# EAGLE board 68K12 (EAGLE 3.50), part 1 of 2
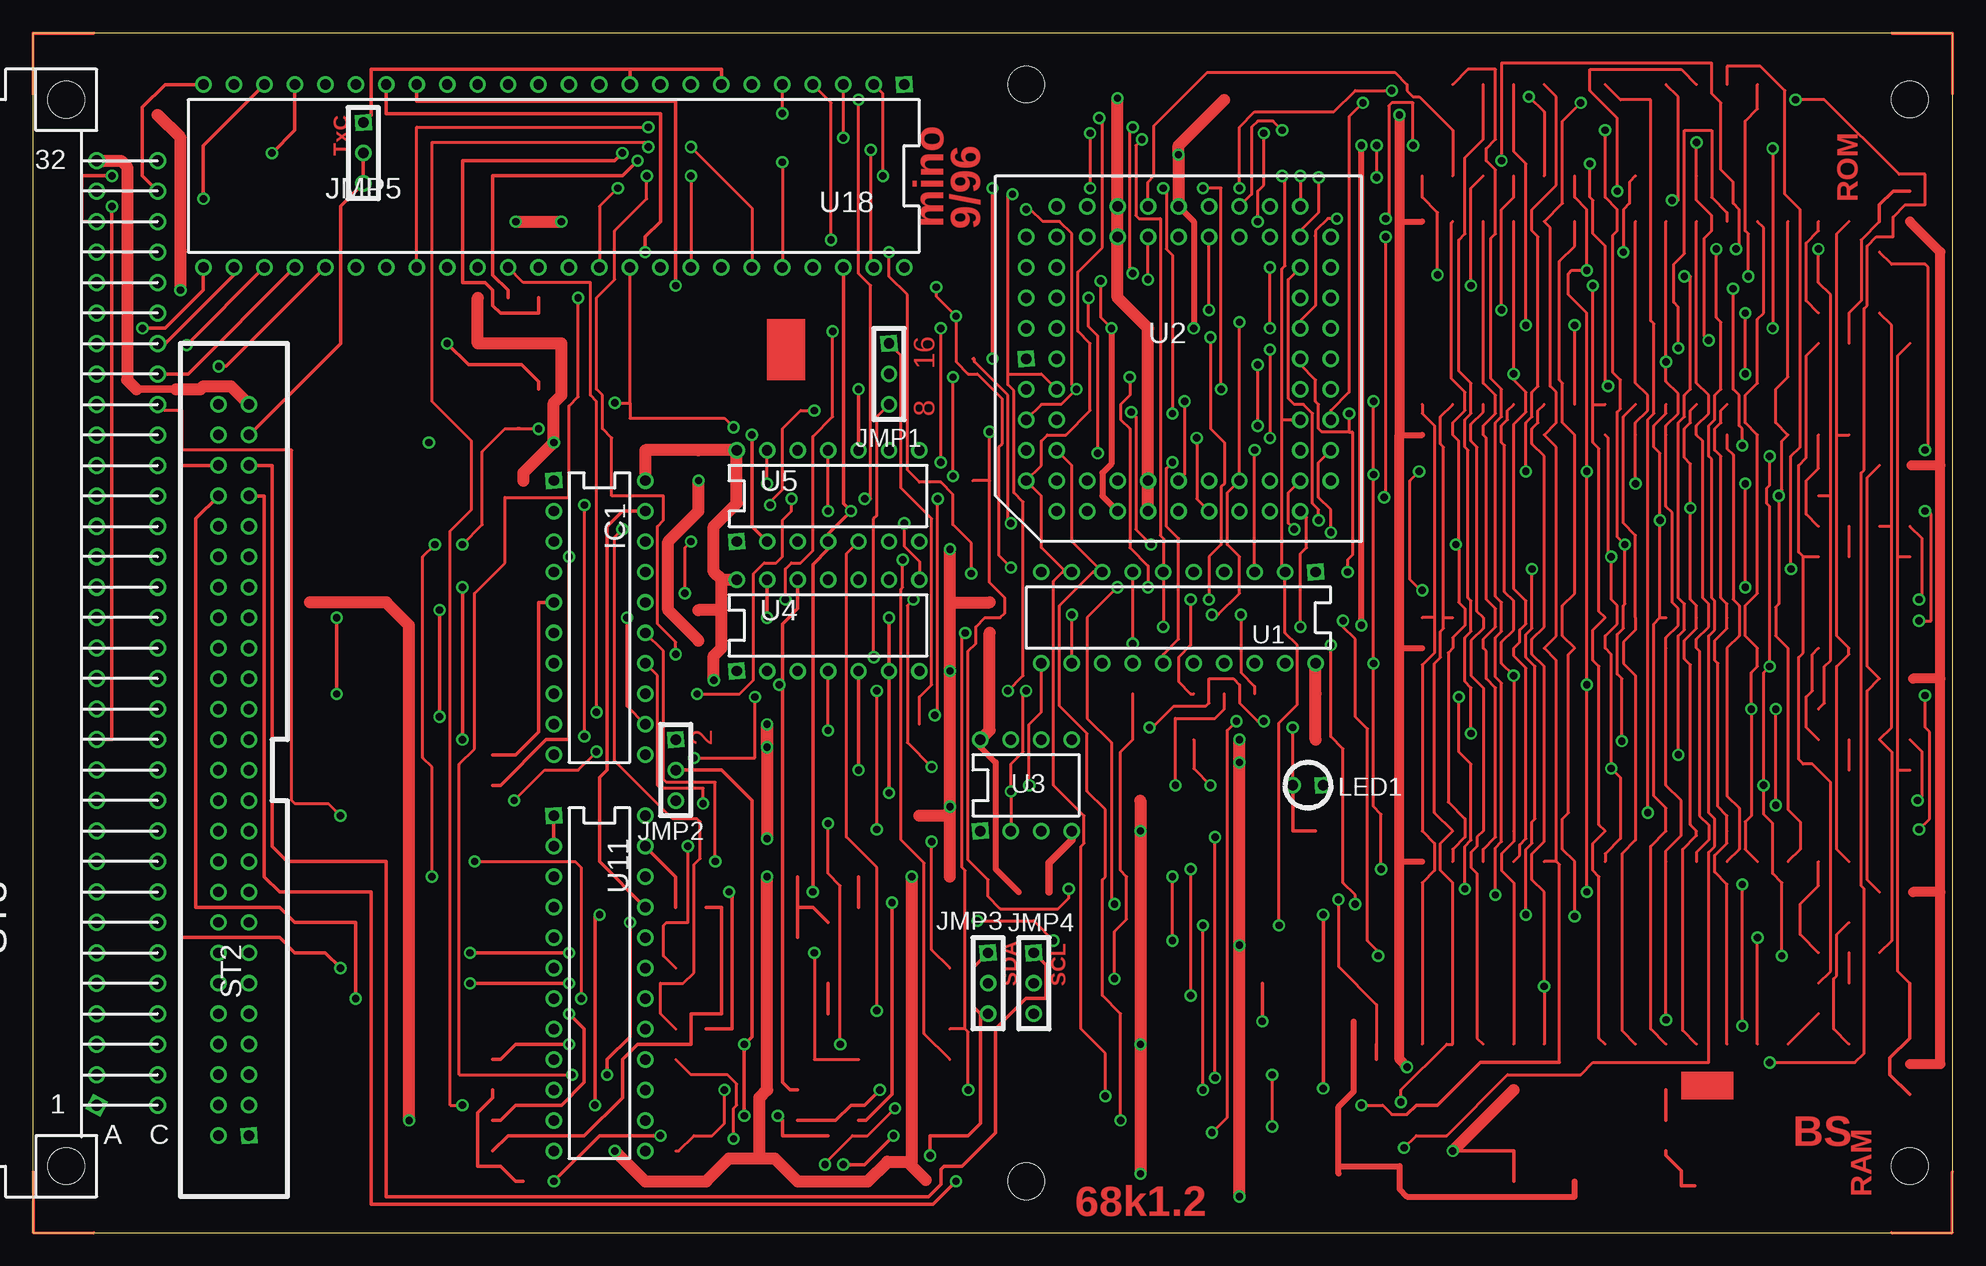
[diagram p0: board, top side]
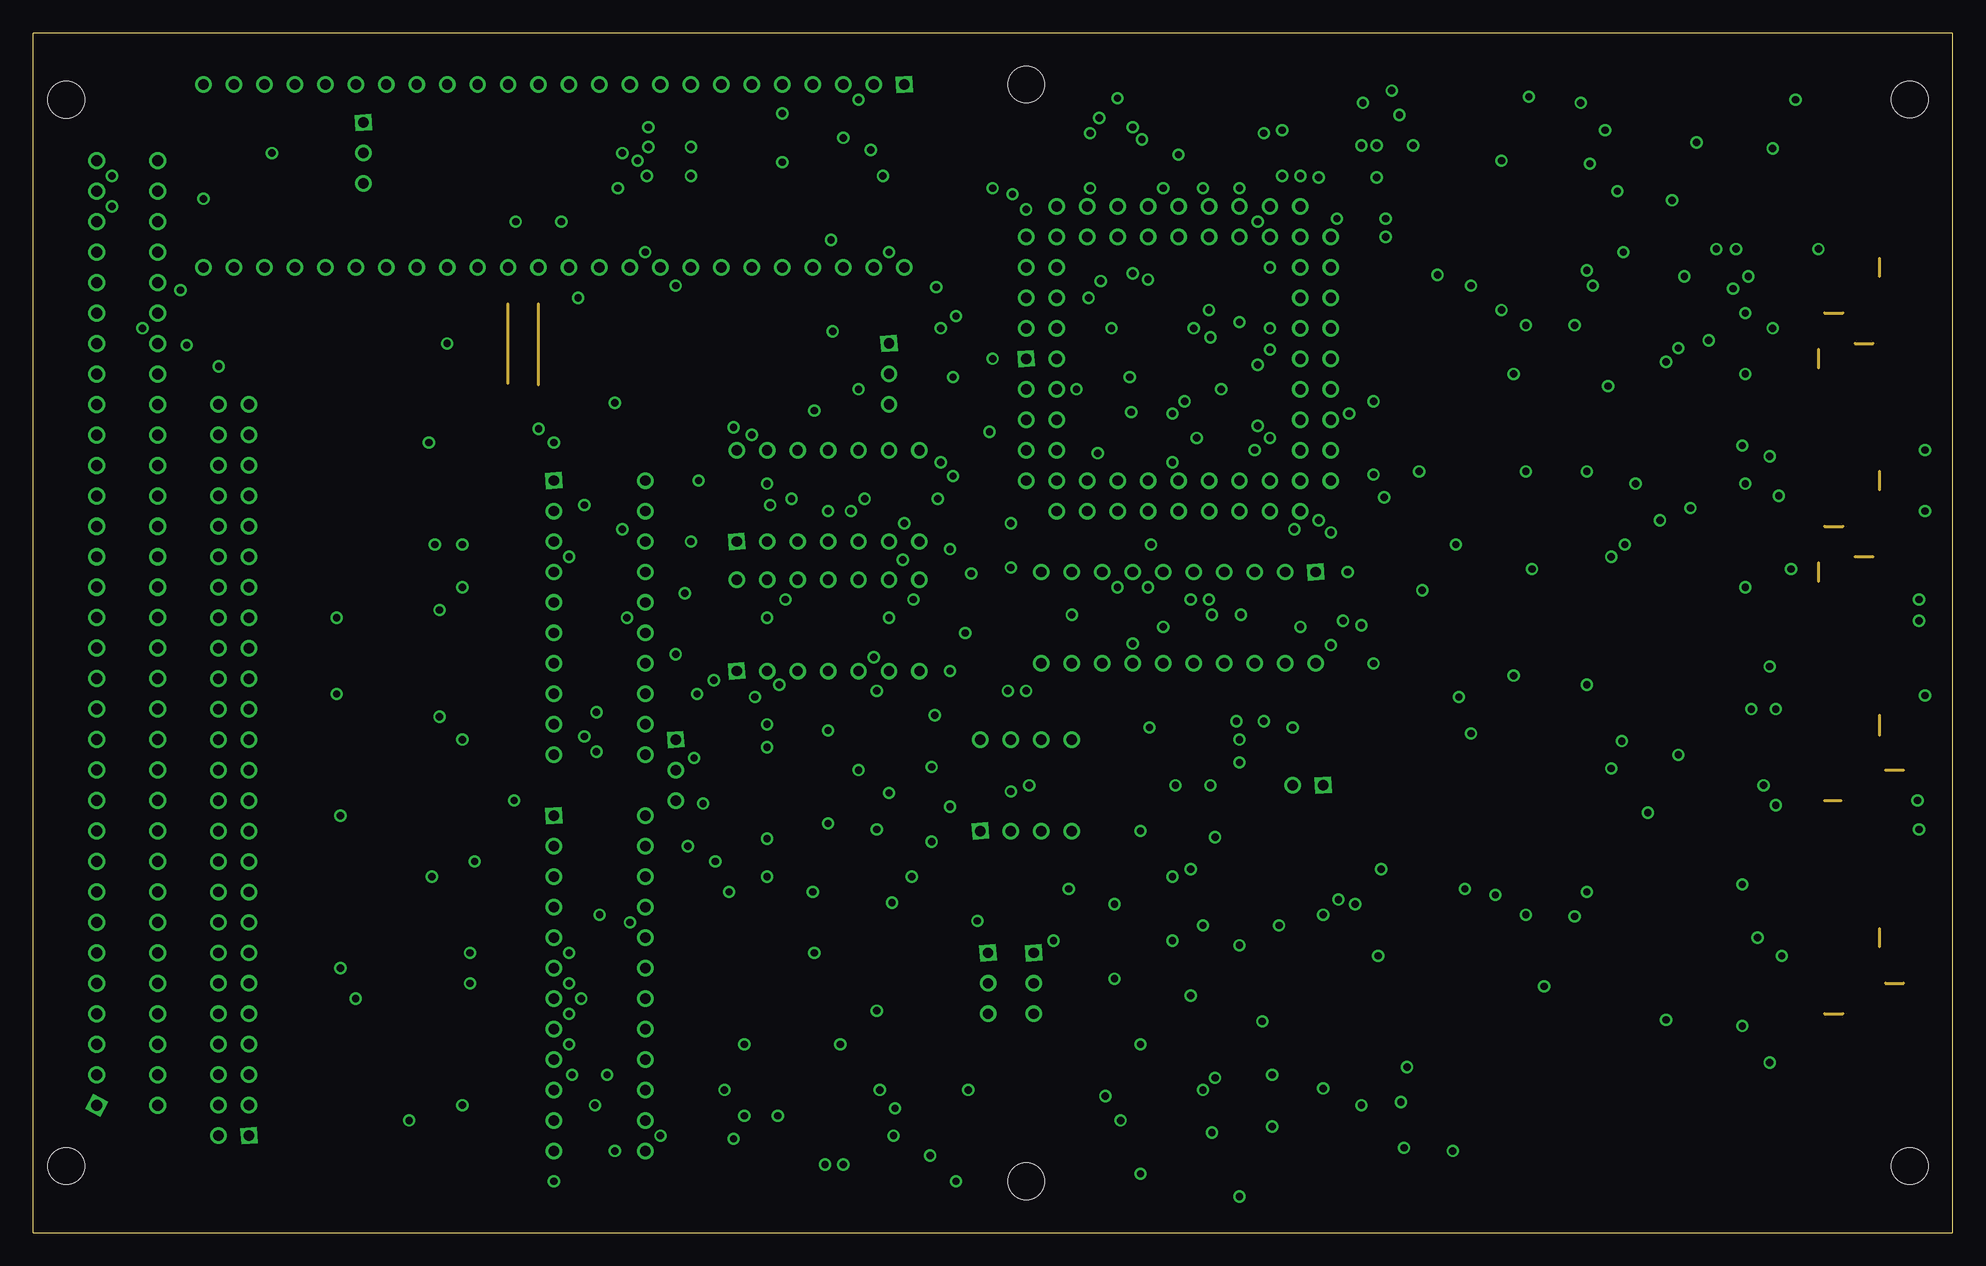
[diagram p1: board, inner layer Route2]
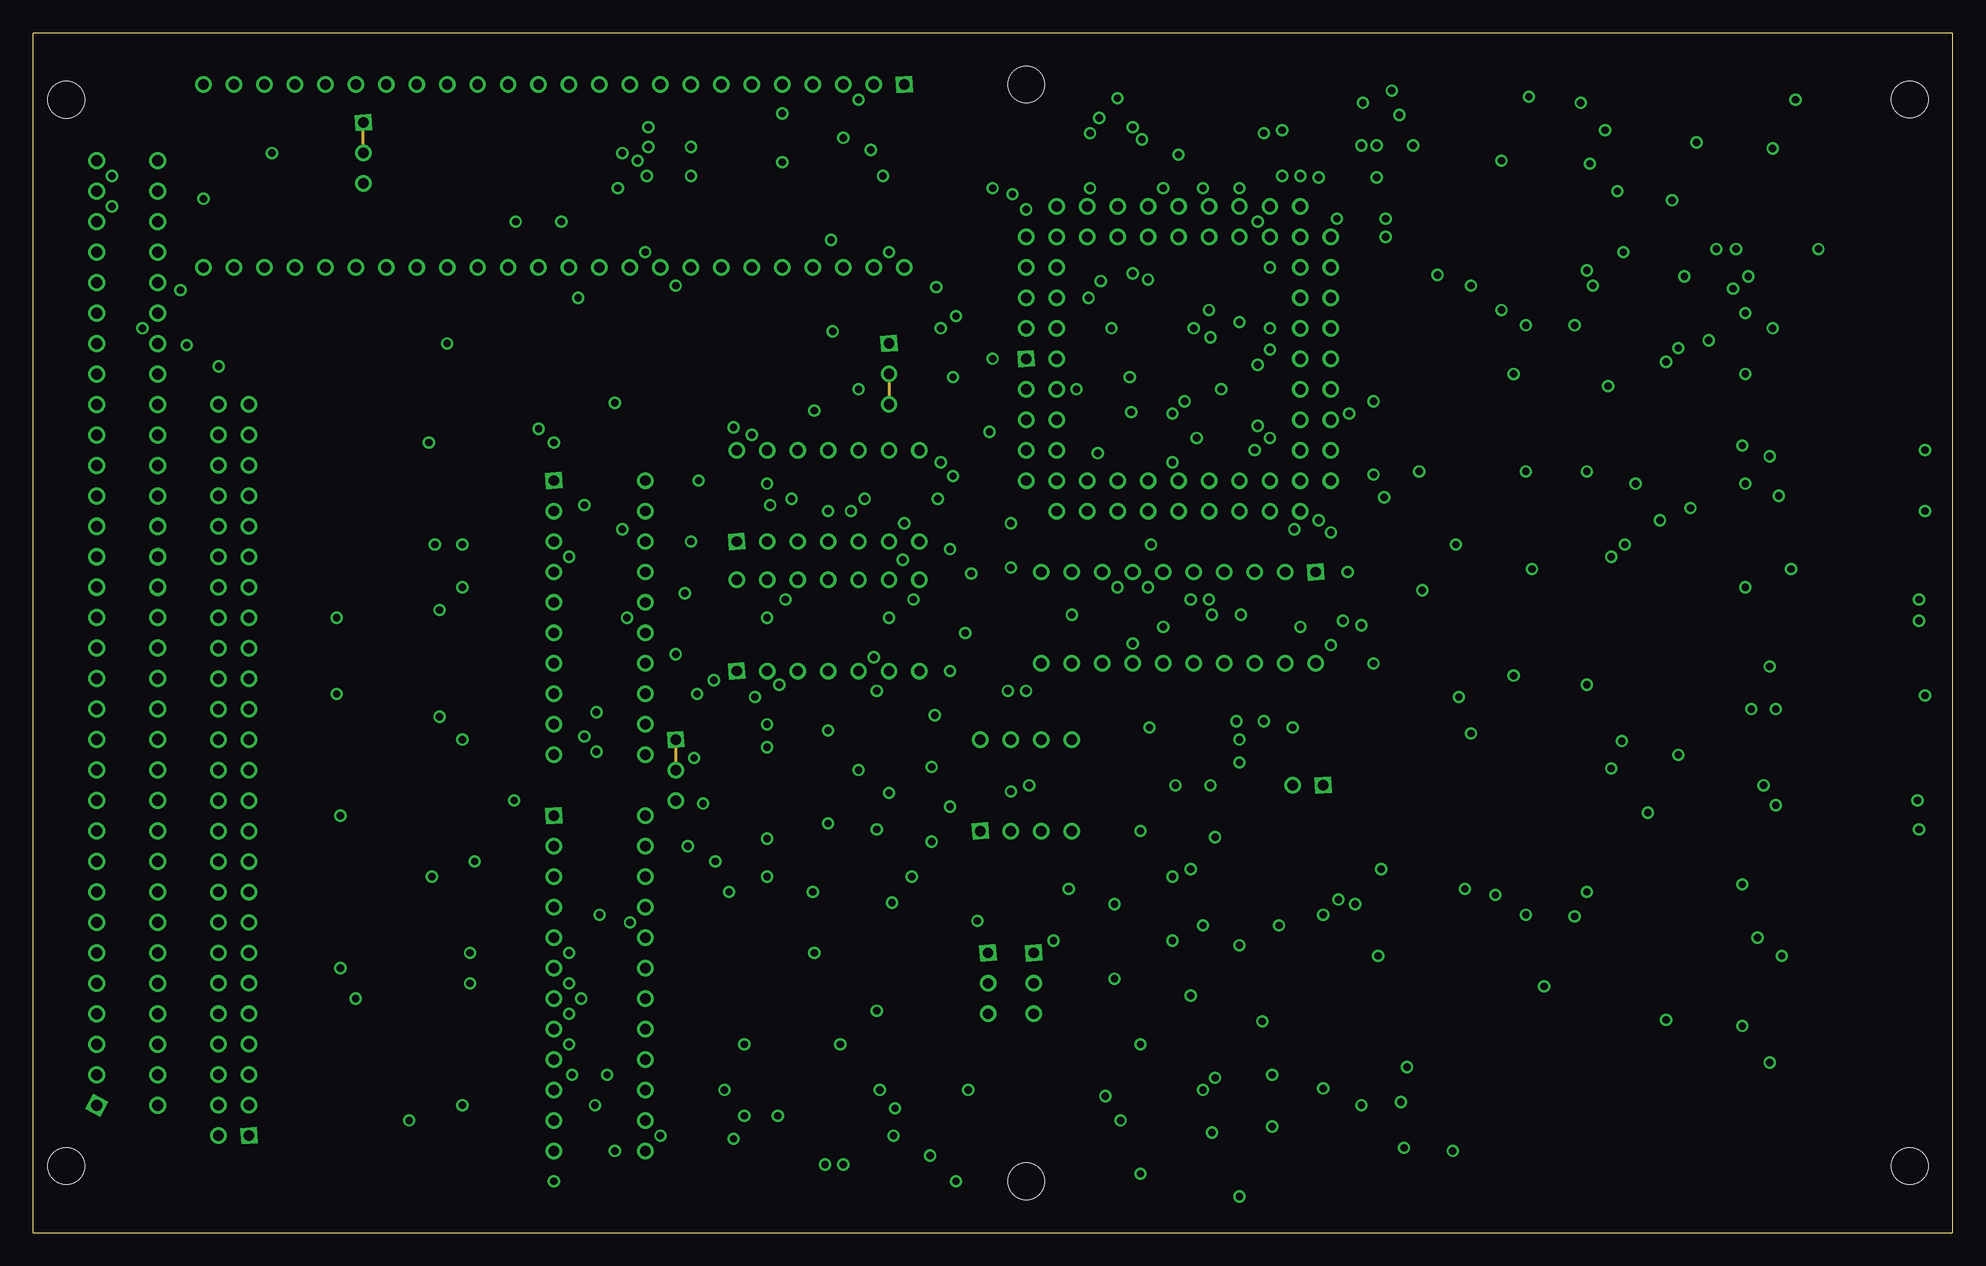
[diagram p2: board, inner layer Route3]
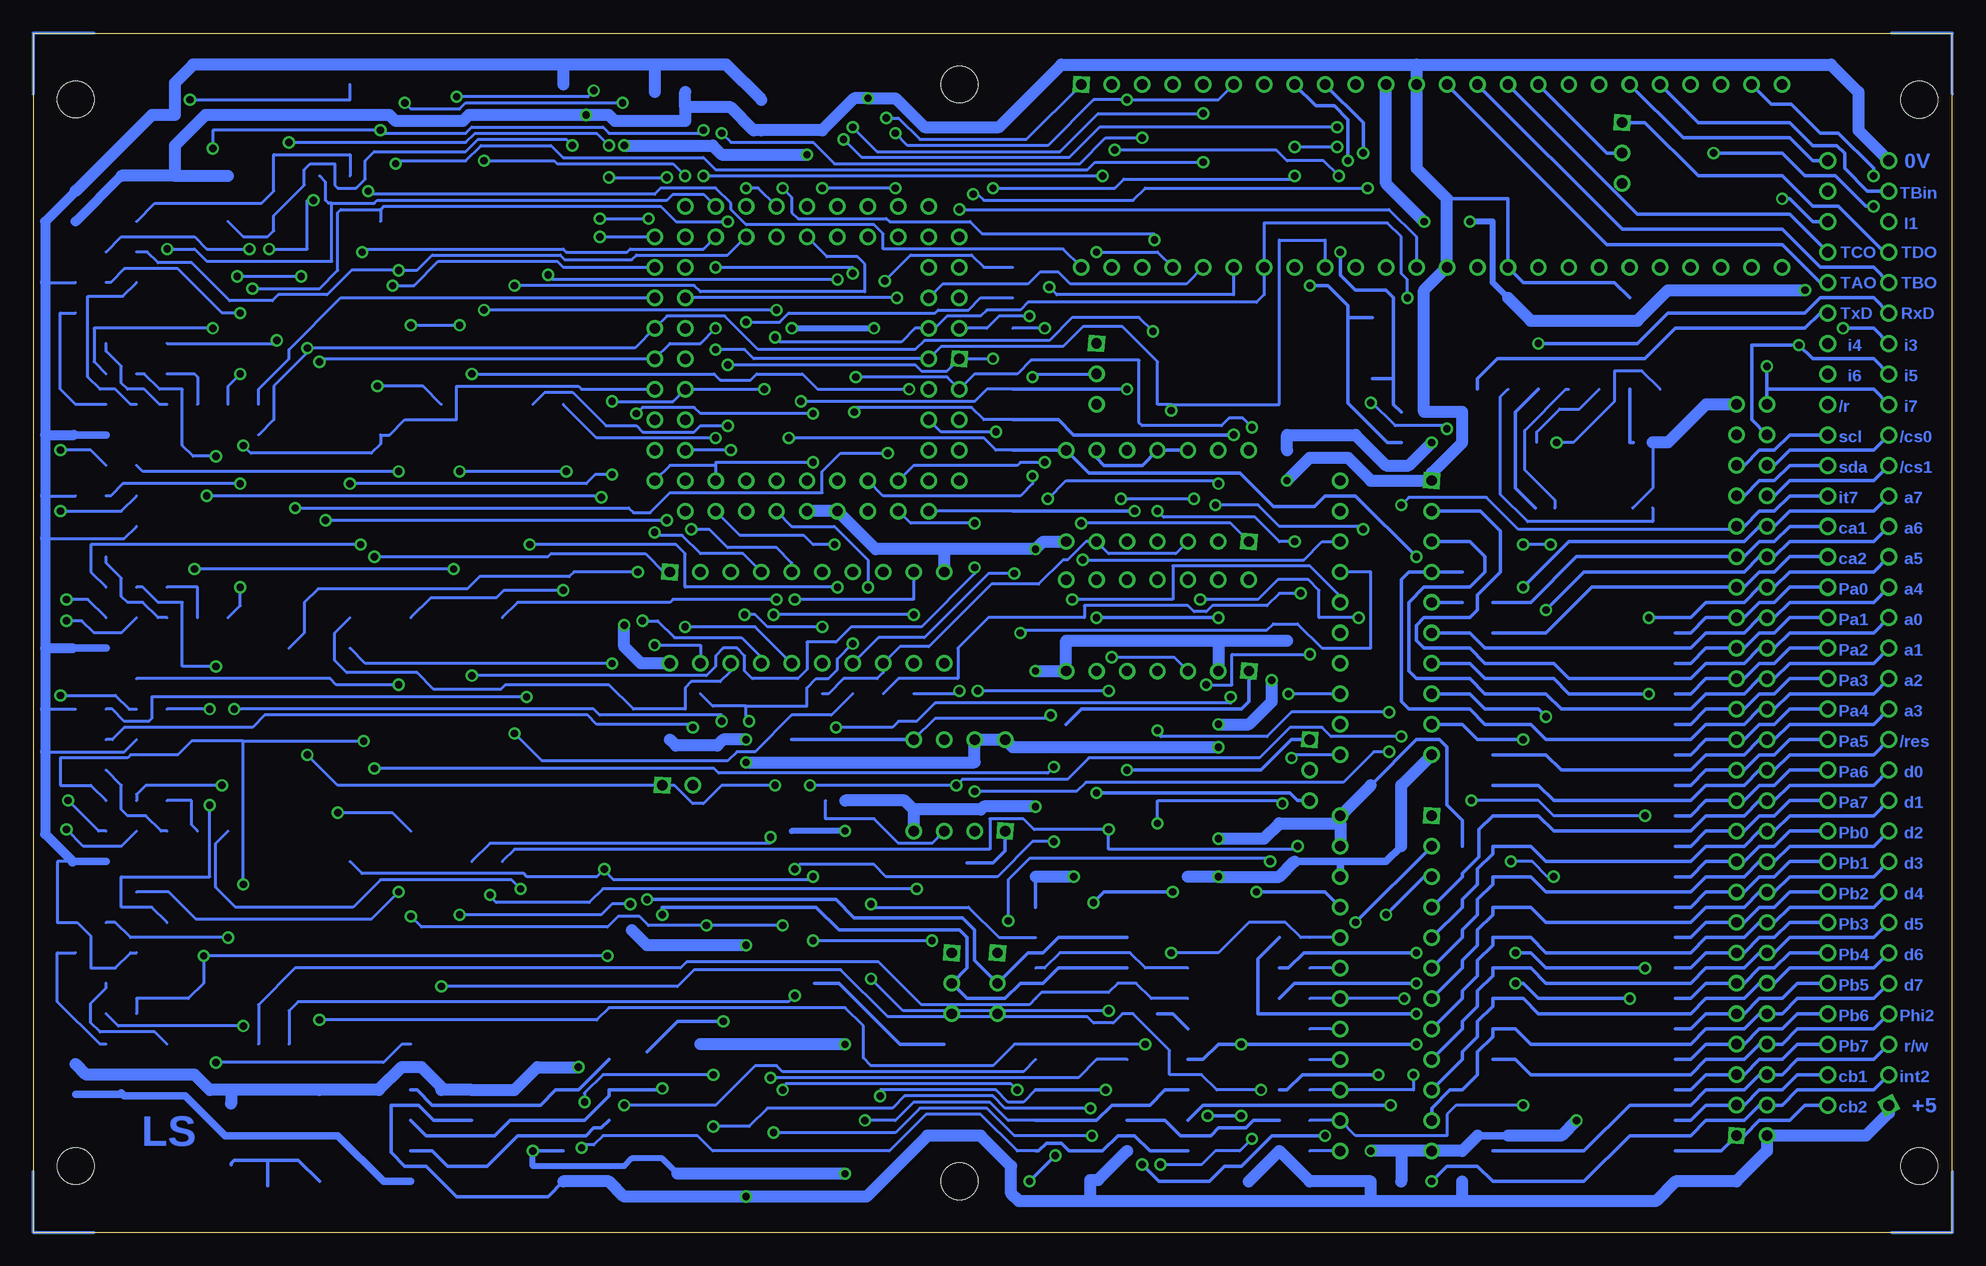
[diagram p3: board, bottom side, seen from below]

Size 159.99 x 100 mm. Coordinates in mm from the lower left corner, seen from the top.
Outline: 0,0 159.99,0 159.99,100 0,100 0,0
Copper layers used: Top, Route2, Route3, Bottom
Holes 3.05 mm at 156.44,5.54 156.44,94.46 82.78,95.71 82.78,4.27
tRestrict: area 49.8,69 to 65,79.2; area 80.2,1.7 to 85.4,6.9; area 80.2,93.1 to 85.4,98.3; area 153.6,2.7 to 159.3,8.4; area 153.6,91.6 to 159.3,97.3
bRestrict: area 80.2,1.7 to 85.4,6.9; area 80.2,93.1 to 85.4,98.3; area 153.6,2.7 to 159.3,8.4; area 153.6,91.6 to 159.3,97.3

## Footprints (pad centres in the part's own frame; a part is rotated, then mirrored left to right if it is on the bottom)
L20 = drill 0.864 pad 1.321 square:  0,0 | drill 0.864 pad 1.321 round:  2.54,0;  5.08,0;  7.62,0;  10.16,0;  12.7,0;  15.24,0;  17.78,0;  20.32,0;  22.86,0;  22.86,7.62;  20.32,7.62;  17.78,7.62;  15.24,7.62;  12.7,7.62;  10.16,7.62;  7.62,7.62;  5.08,7.62;  2.54,7.62;  0,7.62
1 = drill 0.864 pad 1.321 square:  0,0 | drill 0.864 pad 1.321 round:  2.54,0;  5.08,0
D3 = drill 0.864 pad 1.321 square:  0,0 | drill 0.864 pad 1.321 round:  2.54,0
NNE50S = drill 0.864 pad 1.321 square:  3.81,2.54 | drill 0.864 pad 1.321 round:  3.81,5.08;  6.35,2.54;  6.35,5.08;  8.89,2.54;  8.89,5.08;  11.43,2.54;  11.43,5.08;  13.97,2.54;  13.97,5.08;  16.51,2.54;  16.51,5.08;  19.05,2.54;  19.05,5.08;  21.59,2.54;  21.59,5.08;  24.13,2.54;  24.13,5.08;  26.67,2.54;  26.67,5.08;  29.21,2.54;  29.21,5.08;  31.75,2.54;  31.75,5.08;  34.29,2.54;  34.29,5.08;  36.83,2.54;  36.83,5.08;  39.37,2.54;  39.37,5.08;  41.91,2.54;  41.91,5.08;  44.45,2.54;  44.45,5.08;  46.99,2.54;  46.99,5.08;  49.53,2.54;  49.53,5.08;  52.07,2.54;  52.07,5.08;  54.61,2.54;  54.61,5.08;  57.15,2.54;  57.15,5.08;  59.69,2.54;  59.69,5.08;  62.23,2.54;  62.23,5.08;  64.77,2.54;  64.77,5.08
64ACST = drill 0.914 pad 1.422 square:  0,0 | drill 0.914 pad 1.422 round:  0,2.54;  0,5.08;  0,7.62;  0,10.16;  0,12.7;  0,15.24;  0,17.78;  0,20.32;  0,22.86;  0,25.4;  0,27.94;  0,30.48;  0,33.02;  0,35.56;  0,38.1;  0,40.64;  0,43.18;  0,45.72;  0,48.26;  0,50.8;  0,53.34;  0,55.88;  0,58.42;  0,60.96;  0,63.5;  0,66.04;  0,68.58;  0,71.12;  0,73.66;  0,76.2;  0,78.74;  5.08,0;  5.08,2.54;  5.08,5.08;  5.08,7.62;  5.08,10.16;  5.08,12.7;  5.08,15.24;  5.08,17.78;  5.08,20.32;  5.08,22.86;  5.08,25.4;  5.08,27.94;  5.08,30.48;  5.08,33.02;  5.08,35.56;  5.08,38.1;  5.08,40.64;  5.08,43.18;  5.08,45.72;  5.08,48.26;  5.08,50.8;  5.08,53.34;  5.08,55.88;  5.08,58.42;  5.08,60.96;  5.08,63.5;  5.08,66.04;  5.08,68.58;  5.08,71.12;  5.08,73.66;  5.08,76.2;  5.08,78.74 | hole 3.048: -2.54,-5.08; -2.54,83.82
P20 = drill 0.864 pad 1.321 square:  0,0 | drill 0.864 pad 1.321 round:  2.54,0;  5.08,0;  7.62,0;  10.16,0;  12.7,0;  15.24,0;  17.78,0;  20.32,0;  22.86,0;  22.86,7.62;  20.32,7.62;  17.78,7.62;  15.24,7.62;  12.7,7.62;  10.16,7.62;  7.62,7.62;  5.08,7.62;  2.54,7.62;  0,7.62
CC68 = drill 0.864 pad 1.321 square:  10.16,0 | drill 0.864 pad 1.321 round:  10.16,2.54;  12.7,0;  12.7,2.54;  15.24,0;  15.24,2.54;  17.78,0;  17.78,2.54;  20.32,0;  22.86,2.54;  20.32,2.54;  22.86,5.08;  20.32,5.08;  22.86,7.62;  20.32,7.62;  22.86,10.16;  20.32,10.16;  22.86,12.7;  20.32,12.7;  22.86,15.24;  20.32,15.24;  22.86,17.78;  20.32,17.78;  22.86,20.32;  20.32,20.32;  22.86,22.86;  20.32,25.4;  20.32,22.86;  17.78,25.4;  17.78,22.86;  15.24,25.4;  15.24,22.86;  12.7,25.4;  12.7,22.86;  10.16,25.4;  10.16,22.86;  7.62,25.4;  7.62,22.86;  5.08,25.4;  5.08,22.86;  2.54,25.4;  2.54,22.86;  0,25.4;  -2.54,22.86;  0,22.86;  -2.54,20.32;  0,20.32;  -2.54,17.78;  0,17.78;  -2.54,15.24;  0,15.24;  -2.54,12.7;  0,12.7;  -2.54,10.16;  0,10.16;  -2.54,7.62;  0,7.62;  -2.54,5.08;  0,5.08;  -2.54,2.54;  0,0;  0,2.54;  2.54,0;  2.54,2.54;  5.08,0;  5.08,2.54;  7.62,0;  7.62,2.54
L8 = drill 0.864 pad 1.321 square:  0,0 | drill 0.864 pad 1.321 round:  2.54,0;  5.08,0;  7.62,0;  7.62,7.62;  5.08,7.62;  2.54,7.62;  0,7.62
L14 = drill 0.864 pad 1.321 square:  0,0 | drill 0.864 pad 1.321 round:  2.54,0;  5.08,0;  7.62,0;  10.16,0;  12.7,0;  15.24,0;  15.24,7.62;  12.7,7.62;  10.16,7.62;  7.62,7.62;  5.08,7.62;  2.54,7.62;  0,7.62
L24S = drill 0.864 pad 1.321 square:  0,0 | drill 0.864 pad 1.321 round:  2.54,0;  5.08,0;  7.62,0;  10.16,0;  12.7,0;  15.24,0;  17.78,0;  20.32,0;  22.86,0;  25.4,0;  27.94,0;  27.94,7.62;  25.4,7.62;  22.86,7.62;  20.32,7.62;  17.78,7.62;  15.24,7.62;  12.7,7.62;  10.16,7.62;  7.62,7.62;  5.08,7.62;  2.54,7.62;  0,7.62
P48 = drill 0.864 pad 1.321 square:  0,0 | drill 0.864 pad 1.321 round:  2.54,0;  5.08,0;  7.62,0;  10.16,0;  12.7,0;  15.24,0;  17.78,0;  20.32,0;  22.86,0;  25.4,0;  27.94,0;  30.48,0;  33.02,0;  35.56,0;  38.1,0;  40.64,0;  43.18,0;  45.72,0;  48.26,0;  50.8,0;  53.34,0;  55.88,0;  58.42,0;  58.42,15.24;  55.88,15.24;  53.34,15.24;  50.8,15.24;  48.26,15.24;  45.72,15.24;  43.18,15.24;  40.64,15.24;  38.1,15.24;  35.56,15.24;  33.02,15.24;  30.48,15.24;  27.94,15.24;  25.4,15.24;  22.86,15.24;  20.32,15.24;  17.78,15.24;  15.24,15.24;  12.7,15.24;  10.16,15.24;  7.62,15.24;  5.08,15.24;  2.54,15.24;  0,15.24

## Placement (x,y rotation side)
BATT  CR2330  [23XX]  98.02,15.7 0 top
C1  .1u  [P100QA]  79.73,52.53 270 top
C2  .1u  [P100QA]  105.64,95.07 0 top
C3  .1u  [P100QA]  84.68,28.4 180 top
C4  .1u  [P100QA]  55.47,49.35 90 top
C5  .1u  [P100QA]  55.47,62.69 90 top
C6  .1u  [P100QA]  148.18,90.63 90 top
C7  .1u  [P100QA]  156.44,84.28 90 top
C8  .1u  [P100QA]  156.57,63.96 90 top
C9  .1u  [P100QA]  156.69,46.18 90 top
C10  .1u  [P100QA]  156.69,28.4 90 top
C11  .1u  [P100QA]  45.95,4.27 0 top
C12  .1u  [P100QA]  45.95,37.29 0 top
C13  .1u  [P100QA]  56.11,4.27 0 top
C14  .1u  [P100QA]  40.87,6.81 270 top
C15  .1u  [P100QA]  74.4,4.39 180 top
C16  .1u  [P100QA]  125.96,11.89 270 top
C17  .1u  [P100QA]  156.44,14.05 270 top
C18  .1u  [P100QA]  7.85,93.17 0 top
C19  100uF  [P100RA]  99.29,91.9 90 top
C20  .1u  [P100QA]  84.68,30.81 180 top
C21  10uF  [K_MINI]  92.3,36.02 0 top
C22  10p  [P200QA]  66.27,25.86 270 top
C23  10uF  [K_MINI]  152.63,13.16 270 top
C24  27pF  [P200QA]  40.87,65.86 0 top
C25  27pF  [P200QA]  40.87,68.4 0 top
C26  10uF  [K_MINI]  34.65,65.86 180 top
C27  10uF  [K_MINI]  34.77,60.4 180 top
C28  10uF  [K_MINI]  24.99,65.86 0 top
C29  10uF  [K_MINI]  24.99,60.4 0 top
CTR1  5-30pF  [TRIMM]  143.48,5.66 0 top
D1  SD103  [P300IV]  110.08,25.22 270 top
D2  1N4148  [P300IV]  94.84,20.78 0 top
IC1  74HCT245  [L20]  43.41,62.69 270 top
JMP1  ST_3X1  [1]  71.35,74.12 270 top
JMP2  ST_3X1  [1]  53.57,41.1 270 top
JMP3  [1]  79.6,23.32 270 top
JMP4  [1]  83.41,23.32 270 top
JMP5  [1]  27.53,92.53 270 top
JMP7  [LECT]  153.9,76.66 90 top
JMP8  [LECT]  153.9,58.88 90 top
JMP9  [LECT]  153.9,41.1 90 top
JMP10  [LECT]  153.9,23.32 90 top
LED1  LED3MM  [D3]  107.54,37.29 180 top
Q1  16MHz  [_OSZI]  58.65,34.75 0 top
Q2  2.45MHz  []  48.36,78.82 270 top
Q3  32kHz  [X8]  140.44,3.89 90 top
R1  470  [P400IL]  96.75,41.1 0 top
R2  3k3  [P400IL]  96.75,33.48 0 top
R3  3k3  [P400IL]  66.27,8.08 90 top
R4  10k  [P400IL]  108.81,4.9 90 top
RN1  3k3  [P100QA]  78.33,80.47 270 top
RN2  3k3  [P100QA]  106.91,44.91 180 top
RN3  3k3  [P100QA]  53.57,27.13 270 top
RN4  3k3  [P100QA]  40.87,32.21 270 top
RN5  3k3  [P100QA]  40.87,62.69 270 top
RN6  3k3  [P100QA]  111.99,4.27 90 top
ST2  WANNE50S  [NNE50S]  20.55,4.27 90 top
ST3  VG64ACST  [64ACST]  5.31,10.62 0 top
U1  IAK68001  [P20]  106.91,55.07 180 top
U2  68HC001  [CC68]  82.78,83.01 270 top
U3  TL7705  [L8]  78.97,33.48 0 top
U4  74HCT393  [L14]  58.65,46.81 0 top
U5  74HCT05  [L14]  58.65,57.61 0 top
U6  ADR68001  [P24]  115.8,88.09 0 top
U7  RAM_ROM  [P32]  153.9,84.28 180 top
U8  RAM_ROM  [P32]  153.9,66.5 180 top
U9  RAM_ROM  [P32]  153.9,48.72 180 top
U10  RAM_ROM  [P32]  153.9,30.94 180 top
U11  74HCT646  [L24S]  43.41,34.75 270 top
U13  SYN68001  [P20']  63.73,6.81 90 top
U14  65C22  [P40]  23.09,52.53 270 top
U15  IIC68001  [P20']  76.43,6.81 90 top
U16  ST24C02  [L8']  123.42,4.27 90 top
U17  PCF8583  [L8']  136.12,4.27 90 top
U18  68HC901  [P48]  72.62,95.71 180 top
U19  MAX232  [L16]  24.36,70.31 0 top

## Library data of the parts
BATT CTR1 Q1-Q3 U16 U17 U19 = MINO
C1-C29 D1 D2 R1-R4 RN1-RN6 = DISCRETE
IC1 U4 U5 = M74499
JMP1-JMP5 ST2 = CONNEC
JMP7-JMP10 U6-U10 U13-U15 = MOTO
LED1 U3 = ANALOG
ST3 = CONVG64
U1 U18 = MOT
U2 = MIKRO
U11 = M745XX

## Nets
1MHZ: JMP2. U4.
2: BATT.S D2.
2MHZ: JMP2. U4.
4MHZ: U4. U18.
8MHZ: JMP1. U4.
16MHZ: JMP1. Q1. U4.
+: D2. R4.
/ADR_INH: U1. U6.
/AS: RN1. U2. U6.
/BERR: RN1. U2. U5.
/CS0: ST2. ST3. U13.
/CS1: ST2. ST3. U13.
/CS_65XX: U6. U13. U15.
/CS_901: U6. U18.
/CS_6522: U13. U14.
/DS: U1. U2. U4. U13. U15. U18.
/DT_INH: RN2. U1. U5.
/DT_RAM: RN2. U5. U6.
/DTACK: RN1. U2. U5. U13. U15. U18.
/HALT: RN1. U2. U5.
/IAK_901: U1. U18.
/INIT: LED1. R1. U3. U5. U6.
/INT2: RN2. ST2. ST3. U1. U14.
/INT5: RN2. U1. U18.
/INT7: RN2. ST2. ST3. U1.
/Q1: IC1. U11. U13.
/RD: U1. U7. U8. U9. U10.
/RES_IN: RN2. ST3. U3.
/RESET: RN1. ST2. ST3. U2. U5. U14. U15. U18.
/VPA: RN1. U1. U2.
/WR: JMP7. JMP8. JMP9. JMP10. U1.
A0: IC1. U2. U7. U8. U9. U10. U15.
A1: IC1. U1. U2. U7. U8. U9. U10. U15. U18.
A2: IC1. U1. U2. U7. U8. U9. U10. U18.
A3: IC1. U2. U7. U8. U9. U10. U18.
A4: IC1. U2. U7. U8. U9. U10. U18.
A5: IC1. U2. U7. U8. U9. U10. U18.
A6: IC1. U2. U7. U8. U9. U10.
A7: IC1. U2. U7. U8. U9. U10.
A8: U2. U7. U8. U9. U10. U13. U15.
A9: U2. U7. U8. U9. U10. U13. U15.
A10: U2. U7. U8. U9. U10.
A11: U2. U7. U8. U9. U10.
A12: U2. U7. U8. U9. U10.
A13: JMP7. JMP8. JMP9. JMP10. U2. U6.
A14: JMP7. JMP8. JMP9. JMP10. U2. U6.
A15: JMP7. JMP8. JMP9. JMP10. U2. U6.
A16: U2. U6. U7. U8. U9. U10.
A17: JMP7. JMP8. JMP9. JMP10. U2. U6.
A18: JMP7. JMP8. JMP9. JMP10. U2. U6.
A19: U2. U6.
A20: U2. U6.
A21: U2. U6.
A22: U2. U6.
A23: U2. U6.
AX0: IC1. RN5. ST2. ST3. U14.
AX1: IC1. RN5. ST2. ST3. U14.
AX2: IC1. RN5. ST2. ST3. U14.
AX3: IC1. RN5. ST2. ST3. U14.
AX4: IC1. RN5. ST2. ST3.
AX5: IC1. RN5. ST2. ST3.
AX6: IC1. RN5. ST2. ST3.
AX7: IC1. RN5. ST2. ST3.
CA1: ST2. ST3. U14.
CA2: ST2. ST3. U14.
CB1: ST2. ST3. U14.
CB2: ST2. ST3. U14.
CPU_CLK: JMP1. U2.
CS2: JMP7. JMP8. JMP9. JMP10. LED1. R2.
CS_SCL: U15.
D0: RN3. U2. U7. U8. U9. U10. U11. U15. U18.
D1: RN3. U2. U7. U8. U9. U10. U11. U18.
D2: RN3. U2. U7. U8. U9. U10. U11. U18.
D3: RN3. U2. U7. U8. U9. U10. U11. U18.
D4: RN3. U2. U7. U8. U9. U10. U11. U18.
D5: RN3. U2. U7. U8. U9. U10. U11. U18.
D6: RN3. U2. U7. U8. U9. U10. U11. U18.
D7: RN3. U2. U7. U8. U9. U10. U11. U18.
DX0: RN4. ST2. ST3. U11. U14.
DX1: RN4. ST2. ST3. U11. U14.
DX2: RN4. ST2. ST3. U11. U14.
DX3: RN4. ST2. ST3. U11. U14.
DX4: RN4. ST2. ST3. U11. U14.
DX5: RN4. ST2. ST3. U11. U14.
DX6: RN4. ST2. ST3. U11. U14.
DX7: RN4. ST2. ST3. U11. U14.
FC0: U1. U2.
FC1: U1. U2.
FC2: U1. U2.
GND: BATT.US C1. C2. C3. C4. C5. C6. C7. C8. C9. C10. C11. C12. C13. C14. C15. C16. C17. C18. C19. C20. C21. C22. C23. C24. C25. C28. C29. CTR1. IC1. Q1. R2. ST2. ST3. U1. U2. U3. U4. U5. U6. U7. U8. U9. U10. U11. U13. U14. U15. U16. U17. U18. U19.
I0: ST3. U18.
I1: ST3. U18.
I2: ST3. U18.
I3: ST3. U18.
I4: ST3. U18.
I5: ST2. ST3. U18.
I6: ST3. U18.
I7: ST2. ST3. U18.
N$1: JMP7. U7.
N$2: JMP7. U7.
N$3: JMP7. U7.
N$4: U1. U2.
N$6: U1. U2.
N$7: RN1. U2.
N$8: RN1. U2.
N$10: JMP7. U7.
N$11: JMP7. U7.
N$12: JMP7. U7.
N$13: C25. Q2. U18.
N$14: RN2. U5.
N$15: U4. U5.
N$16: RN6. U17.
N$17: U18. U19.
N$18: JMP8. U8.
N$19: C24. Q2. U18.
N$20: JMP8. U8.
N$21: JMP8. U8.
N$22: JMP8. U8.
N$23: C20. U3.
N$24: C21. U3.
N$25: JMP8. U8.
N$26: JMP8. U8.
N$27: C28. U19.
N$28: C29. U19.
N$30: C22. R3. U13.
N$32: C27. U19.
N$33: C27. U19.
N$34: U18. U19.
N$55: U6. U7.
N$57: U6. U8.
N$58: JMP9. U9.
N$59: JMP9. U9.
N$60: JMP9. U9.
N$61: JMP9. U9.
N$62: JMP9. U9.
N$63: JMP9. U9.
N$91: U6. U9.
N$92: U6. U10.
N$94: JMP10. U10.
N$95: JMP10. U10.
N$96: JMP10. U10.
N$97: JMP10. U10.
N$98: JMP10. U10.
N$99: JMP10. U10.
PA0: ST2. ST3. U14.
PA1: ST2. ST3. U14.
PA2: ST2. ST3. U14.
PA3: ST2. ST3. U14.
PA4: ST2. ST3. U14.
PA5: ST2. ST3. U14.
PA6: ST2. ST3. U14.
PA7: ST2. ST3. U14.
PB0: ST2. ST3. U14.
PB1: ST2. ST3. U14.
PB2: ST2. ST3. U14.
PB3: ST2. ST3. U14.
PB4: ST2. ST3. U14.
PB5: ST2. ST3. U14.
PB6: ST2. ST3. U14.
PB7: ST2. ST3. U14.
PHI2: JMP2. R3. ST2. ST3. U13. U14.
Q3: U11. U13.
R/W: RN2. U1. U2. U11. U13. U15. U18.
RW_BUF: ST2. ST3. U13. U14.
RXC/TXC: JMP5. ST3. U18.
RXD: ST3. U19.
S$9: Q3. U17.
S$10: CTR1. Q3. U17.
S$11: C26. U19.
S$12: C26. U19.
SCL: JMP4. RN6. U15. U16. U17.
SCL_EXT: JMP4. ST2. ST3.
SDA: JMP3. RN6. U15. U16. U17.
SDA_EXT: JMP3. ST2. ST3.
TAI: ST3. U18.
TAO: ST3. U18.
TBI: ST3. U18.
TBO: ST3. U18.
TCO: ST3. U18.
TDO: JMP5. ST2. U18.
TXD: ST3. U19.
VBATT: C17. C23. D1. JMP7.TT JMP8.TT JMP9.TT JMP10.TT R4. U17.
VCC: C1. C2. C3. C4. C5. C6. C7. C8. C9. C10. C11. C12. C13. C14. C15. C16. C18. C19. D1. IC1. JMP7. JMP8. JMP9. JMP10. Q1. R1. RN1. RN2. RN3. RN4. RN5. RN6. ST2. ST3. U1. U2. U3. U4. U5. U6. U7. U8. U9. U10. U11. U13. U14. U15. U16. U18. U19.

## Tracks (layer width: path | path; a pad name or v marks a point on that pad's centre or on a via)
1MHZ  (via drill 0.61 pad 1.02)
  Top 0.305: v71.35,36.65 71.35,46.81 v71.35,51.26 | v61.19,51.26 61.19,54.43
  Bottom 0.305: JMP2. 54.58,36.02 55.22,36.65 v71.35,36.65 | v71.35,51.26 v61.19,51.26
2
  Bottom 0.305: 94.84,20.78 92.81,20.78 87.73,15.7 84.05,15.7
2MHZ  (via drill 0.61 pad 1.02)
  Top 0.305: v68.81,38.56 68.81,46.81
  Bottom 0.305: v68.81,38.56 57.63,38.56 55.09,41.1 53.57,41.1
4MHZ  (via drill 0.61 pad 1.02)
  Top 0.254: v46.96,43.38 46.96,69.29 46.46,69.8 46.46,79.2 40.87,79.2 39.6,80.47 | v66.27,41.86 66.27,46.81
  Bottom 0.254: v46.96,43.38 55.09,43.38 57.12,41.35 66.01,41.35 66.27,41.61 v66.27,41.86
8MHZ  (via drill 0.61 pad 1.02)
  Top 0.254: JMP1. 70.33,68.02 70.33,59.77 70.08,59.51 v70.08,47.96
  Bottom 0.254: 63.73,46.81 64.87,47.96 v70.08,47.96
16MHZ
  Top 0.254: 71.35,74.12 72.36,73.1 72.36,62.05 74.9,59.51 74.9,45.67 73.89,44.65 73.89,42.37
  Bottom 0.305: 73.89,42.37 72.62,43.64 59.28,43.64 58.65,44.27 58.65,46.81
+  (via drill 0.61 pad 1.02)
  Top 0.305: v102.46,17.6 102.46,20.78
  Bottom 0.305: v102.46,17.6 106.27,17.6 108.81,15.06
/ADR_INH  (via drill 0.61 pad 1.02)
  Top 0.254: v108.18,48.97 108.18,41.35 109.19,40.34 109.19,29.16 110.21,28.14 v110.21,27.38 | v124.43,26.49 124.43,31.95 124.94,32.46 124.94,34.24 125.2,34.49 125.2,47.19 124.43,47.96 124.43,49.86 124.94,50.37 v124.94,55.32 | 141.2,95.71 141.2,97.23 143.99,97.23 146.02,95.2 146.02,86.56 147.29,85.29 147.29,65.48 146.53,64.72 v146.53,55.32
  Bottom 0.254: v108.18,48.97 104.37,48.97 104.37,47.45 | v124.43,26.49 112.62,26.49 111.73,27.38 v110.21,27.38 | v124.94,55.32 v146.53,55.32
/AS  (via drill 0.61 pad 1.02)
  Top 0.254: 79.73,62.69 v79.73,66.75 | 79.73,62.69 78.33,62.69 | 118.34,95.71 119.61,96.98 121.89,96.98 121.89,91.14 121.13,90.37 121.13,89.36 121.89,88.6 121.89,83.26 121.51,82.88 121.51,71.2 122.4,70.31 122.4,68.02 121.89,67.51 121.89,53.04 122.4,52.53 122.4,50.11 121.89,49.61 121.89,46.3 122.4,45.8 122.4,32.59 121.89,32.08 v121.89,28.14 | 79.73,62.69 79.73,54.18 81,52.91 81,51.64 80.62,51.26 79.35,51.26 78.59,50.5 78.59,49.1 77.95,48.46 77.95,31.06 79.6,29.41 79.6,28.02 80.62,27 85.45,27 86.33,27.89 v86.33,28.65
  Bottom 0.254: v79.73,66.75 84.3,66.75 85.32,67.77 | v86.33,28.65 112.5,28.65 113.64,27.51 121.39,27.51 121.89,28.02 v121.89,28.14
/BERR  (via drill 0.61 pad 1.02)
  Top 0.254: v93.19,57.35 91.92,58.62 91.92,68.02 v91.54,68.4
  Top 0.305: v59.92,66.5 59.92,58.88 61.19,57.61
  Bottom 0.254: v93.19,57.35 94.97,57.35 95.73,58.12 101.07,58.12 103.1,60.15 | v91.54,68.4 91.54,68.78 81.76,68.78 80.75,67.77 78.33,67.77
  Bottom 0.305: 78.33,67.77 74.52,67.77 73.25,66.5 v59.92,66.5
/CS0  (via drill 0.61 pad 1.02)
  Top 0.305: v36.42,23.32 v44.68,23.32 | v25.63,22.05 24.36,23.32 21.82,23.32 20.55,24.59 12.29,24.59 12.29,63.96 15.47,63.96
  Bottom 0.305: 5.31,66.5 6.58,65.23 13.56,65.23 14.83,63.96 15.47,63.96 | v44.68,23.32 54.08,23.32 55.35,22.05 56.11,22.05 | v25.63,22.05 33.88,22.05 35.15,23.32 v36.42,23.32
/CS1  (via drill 0.61 pad 1.02)
  Top 0.305: v36.42,20.78 v44.68,20.78 | v26.9,19.51 26.9,25.86 21.82,25.86 20.55,27.13 13.56,27.13 13.56,59.51 15.47,61.42
  Bottom 0.305: 5.31,63.96 6.58,62.69 13.56,62.69 14.83,61.42 15.47,61.42 | 56.11,19.51 54.84,20.78 v44.68,20.78 | v36.42,20.78 35.79,20.78 34.52,19.51 v26.9,19.51
/CS_65XX  (via drill 0.61 pad 1.02)
  Top 0.254: v136.63,86.06 137.13,86.06 137.13,94.69 136.12,95.71 | v114.27,7.06 115.29,8.08 117.83,8.08 122.91,13.16 129.01,13.16 130.02,14.17 139.67,14.17 139.67,31.7 140.18,32.21 140.18,34.49 139.67,35 139.67,49.73 140.18,50.24 140.18,52.65 139.93,52.91 139.93,64.47 139.67,64.72 139.67,67.26 140.18,67.77 140.18,69.8 140.69,70.31 140.69,75.9 140.31,76.28 v140.31,81.99
  Bottom 0.254: v136.63,86.06 137.13,86.06 137.13,81.99 v140.31,81.99 | v114.27,7.06 114.02,7.32 113.26,7.32 112.5,8.08 104.62,8.08 103.35,6.81 88.62,6.81 85.57,9.86 81,9.86 77.95,6.81 76.43,6.81
  Bottom 0.305: 63.73,6.81 66.9,6.81 68.17,8.08 69.57,8.08 70.84,6.81 73.63,6.81 74.27,7.44 75.54,7.44 76.17,6.81 76.43,6.81
/CS_901  (via drill 0.61 pad 1.02)
  Top 0.254: 138.66,95.71 137.39,96.98 129.77,96.98 129.77,95.2 132.05,92.91 v132.05,86.82
  Bottom 0.254: v132.05,86.82 131.8,86.56 108.18,86.56 107.67,87.07 103.1,87.07 101.83,85.8 101.83,85.29 100.56,84.02 89.89,84.02 89.13,83.26 89.13,81.99 74.14,81.99 U18.
/CS_6522  (via drill 0.61 pad 1.02)
  Top 0.305: 38.33,9.35 38.96,9.35 40.23,10.62 44.04,10.62 45.95,12.52 45.95,16.97 v44.68,18.24
  Bottom 0.305: v44.68,18.24 57.89,18.24 57.89,22.81 56.11,24.59
/DS  (via drill 0.61 pad 1.02)
  Top 0.254: v51.16,88.09 51.16,86.18 48.49,83.52 48.49,79.45 46.96,77.93 46.96,70.31 47.47,69.8 47.47,67.01 48.23,66.24 48.23,61.42 52.55,61.42 52.55,59.39 52.04,58.88 52.04,50.75 53.57,49.23 v53.57,48.21 | 62.46,45.67 v62.2,45.67 | v90.65,9.35 90.65,18.24 89.13,19.76 89.13,29.41 89.38,29.67 89.38,35.26 87.86,36.78 87.86,41.61 85.57,43.89 85.57,52.27 88.37,55.07 89.13,55.07 86.59,57.61 86.59,63.96 85.32,65.23 | 70.08,80.47 69.82,80.72 v69.82,90.25
  Top 0.305: 63.73,11.89 63.09,11.89 62.46,12.52 62.46,45.67 62.46,50.75 63.73,52.02 63.73,54.43
  Bottom 0.254: v69.82,90.25 56.36,90.25 55.47,89.36 52.43,89.36 v51.16,88.09 | v53.57,48.21 60.05,48.21 60.05,45.67 v62.2,45.67 | 76.43,9.35 78.71,9.35 80.24,10.87 86.59,10.87 88.11,9.35 v90.65,9.35
  Bottom 0.305: 76.43,9.35 71.35,9.35 70.08,10.62 66.9,10.62 65.63,11.89 63.73,11.89
/DT_INH
  Bottom 0.254: 63.73,57.61 64.74,56.59 70.33,56.59 71.35,57.61 72.24,57.61 73.76,56.08 74.14,56.08 76.17,54.05 80.11,54.05 85.32,48.84 87.73,48.84 89.13,47.45 89.13,46.69 89.64,46.18 92.43,46.18 93.7,44.91 94.21,44.91
/DT_RAM  (via drill 0.61 pad 1.02)
  Top 0.254: 91.67,44.91 91.67,41.1 90.65,40.08 90.65,30.18 91.16,29.67 91.16,26.11 90.14,25.1 v90.14,21.16 | v70.33,18.49 70.33,30.43 67.79,32.97 67.79,56.59 68.81,57.61 | 120.88,95.71 120.88,91.14 119.35,89.61 119.35,83.26 118.85,82.75 118.85,71.83 119.86,70.82 119.86,68.28 119.35,67.77 119.35,65.48 119.61,65.23 119.61,52.91 119.86,52.65 119.86,50.11 119.35,49.61 119.35,45.92 119.86,45.42 v119.86,41.61
  Bottom 0.254: v90.14,21.16 87.48,18.49 v70.33,18.49 | v119.86,41.61 117.58,39.32 102.08,39.32 101.32,40.08 99.8,40.08 96.75,43.13 93.45,43.13 91.67,44.91
/DTACK  (via drill 0.61 pad 1.02)
  Top 0.305: 67.54,80.47 67.54,60.78 v68.17,60.15 66.27,58.24 66.27,57.61 66.27,56.97 65,55.7 v65,28.4 | v71.6,27.51 71.6,11.51 69.44,9.35 68.81,9.35
  Bottom 0.254: 78.33,60.15 85.32,60.15
  Bottom 0.305: 68.81,9.35 65.63,9.35 64.36,8.08 61.82,8.08 61.19,8.71 58.9,8.71 58.27,9.35 56.11,9.35 | v68.17,60.15 78.33,60.15 | v65,28.4 70.71,28.4 v71.6,27.51
/HALT  (via drill 0.61 pad 1.02)
  Top 0.254: v95.99,69.29 95.99,63.2 95.48,62.69
  Top 0.305: 68.81,65.23 v68.81,70.31
  Bottom 0.254: v95.99,69.29 81.51,69.29 80.49,70.31 78.33,70.31
  Bottom 0.305: v68.81,70.31 78.33,70.31
/IAK_901  (via drill 0.61 pad 1.02)
  Top 0.254: v78.21,54.94 78.21,57.48 76.68,59 76.68,61.54 75.67,62.56 73.89,62.56 72.87,63.58 72.87,78.18 71.35,79.71 v71.35,81.74
  Bottom 0.254: v78.21,54.94 80.37,54.94 85.7,49.61 89.51,49.61 91.67,47.45 | 65,80.47 66.27,81.74 v71.35,81.74
/INIT  (via drill 0.61 pad 1.02)
  Top 0.254: v75.41,61.16 75.41,43.38 v75.16,43.13 | v61.19,62.43 61.19,65.23 | v142.98,79.71 142.98,83.26 142.72,83.52 142.72,92.66 143.74,93.68 143.74,95.71 | v137.64,79.71 138.15,79.71 138.15,70.31 137.64,69.8 137.64,68.02 137.13,67.51 137.13,52.91 137.64,52.4 137.64,50.24 137.13,49.73 v137.13,39.83 | v98.15,37.29 96.75,38.68 96.75,41.1
  Bottom 0.254: v61.19,62.43 61.44,62.69 73.89,62.69 v75.41,61.16 | v75.16,43.13 75.41,42.88 84.81,42.88 86.59,41.1 | v98.15,37.29 102.59,37.29 104.11,35.76 105,35.76 106.53,37.29 107.54,37.29 134.59,37.29 v137.13,39.83 | v137.64,79.71 v142.98,79.71
  Bottom 0.305: 86.59,41.1 96.75,41.1
/INT2  (via drill 0.61 pad 1.02)
  Top 0.254: v91.67,49.1 91.67,55.07 | v98.27,8.33 99.54,9.6 99.54,41.86 v100.3,42.62
  Top 0.305: v52.3,8.08 47.22,8.08 v43.41,4.27 | v67.54,5.66 69.32,5.66 v71.73,8.08
  Bottom 0.254: 100.56,43.89 95.48,43.89 95.48,45.42 94.72,46.18 93.7,46.18 92.94,46.94 92.94,47.83 v91.67,49.1 | 100.56,43.89 103.35,43.89 104.37,44.91 | 100.56,43.89 100.56,42.88 v100.3,42.62 | v71.73,8.08 78.21,8.08 80.49,10.36 86.08,10.36 88.11,8.33 v98.27,8.33
  Bottom 0.305: 5.31,13.16 6.58,11.89 12.93,11.89 14.2,10.62 15.47,10.62 16.1,10.62 17.37,9.35 20.55,9.35 21.82,8.08 26.9,8.08 30.71,4.27 38.33,4.27 39.6,5.54 42.14,5.54 v43.41,4.27 | v52.3,8.08 56.74,8.08 59.28,5.54 60.68,5.54 61.95,4.27 66.14,4.27 v67.54,5.66
/INT5  (via drill 0.61 pad 1.02)
  Top 0.254: v94.21,50.5 94.21,55.07 94.21,57.86 93.95,58.12 93.95,84.53 92.18,84.53 91.92,84.79 91.92,90.63 v92.43,91.14 | 101.83,44.91 101.83,45.54 100.69,46.69 v100.69,51.51 | v51.28,92.15 31.98,92.15 31.98,80.47
  Bottom 0.254: v51.28,92.15 71.09,92.15 73.63,89.61 90.91,89.61 v92.43,91.14 | v100.69,51.51 99.8,51.51 98.78,50.5 v94.21,50.5
/INT7  (via drill 0.61 pad 1.02)
  Top 0.254: v95.22,37.29 95.22,42.88 98.53,42.88 99.29,43.64 99.29,44.91 | v83.03,37.29 83.03,42.37 84.05,43.38 84.05,47.45 | v45.95,60.66 v45.95,41.35
  Bottom 0.254: v45.95,60.66 45.31,61.29 38.84,61.29 36.17,58.62 18.26,58.62 18.01,58.88 | v45.95,41.35 51.79,41.35 52.55,42.11 55.22,42.11 57.76,39.57 71.98,39.57 73.76,37.8 82.52,37.8 v83.03,37.29 v95.22,37.29
  Bottom 0.305: 10.39,61.42 13.56,61.42 14.83,60.15 16.1,60.15 17.37,58.88 18.01,58.88
/Q1  (via drill 0.61 pad 1.02)
  Top 0.305: 56.11,16.97 58.27,16.97 58.27,28.14 v58.01,28.4 | 51.03,27.13 47.22,30.94 47.22,37.92 47.85,38.56 47.85,58.88 49.12,60.15 51.03,60.15
  Bottom 0.305: v58.01,28.4 52.3,28.4 51.03,27.13
/RD
  Top 0.254: 133.58,15.7 132.44,16.84 132.44,31.57 133.58,32.72 133.58,33.48 133.58,46.43 132.56,47.45 132.56,49.23 133.58,50.24 133.58,51.26 133.58,58.12 132.56,59.13 132.56,68.02 133.58,69.04
  Bottom 0.254: 101.83,47.45 101.83,46.81 102.72,45.92 105.13,45.92 105.64,45.42 105.64,43.64 109.96,43.64 111.99,45.67 120.62,45.67 121.01,45.29 126.59,45.29 127.99,46.69 133.83,46.69 134.85,47.7 134.85,49.99 133.58,51.26
/RES_IN  (via drill 0.61 pad 1.02)
  Top 0.254: v25.63,34.75 24.61,35.76 21.82,35.76 21.56,36.02 21.56,65.23 12.42,65.23 12.42,68.53 10.9,68.53 10.39,69.04 | v40.11,36.02 42.65,38.56 45.44,38.56 v46.96,40.08 | 81.51,33.48 v81.51,36.78 81.51,39.07 82.52,40.08 82.52,44.91 v82.78,45.16
  Bottom 0.254: v25.63,34.75 33.25,34.75 34.52,36.02 v40.11,36.02 | v46.96,40.08 48.23,40.08 50.77,37.54 72.24,37.54 73,36.78 v81.51,36.78 | v82.78,45.16 83.03,44.91 86.59,44.91
/RESET  (via drill 0.61 pad 1.02)
  Top 0.254: v97,66.24 97,61.16 98.02,60.15 | v90.14,27.38 89.89,27.64 89.89,40.84 87.86,42.88 87.86,51.26 v90.4,53.8
  Top 0.305: 21.82,95.71 21.82,91.9 v19.91,89.99 | v44.68,56.34 44.68,41.1 42.77,41.1 38.96,37.29 38.33,37.29 | 5.31,41.1 6.58,41.1 v6.58,85.55
  Bottom 0.254: v97,66.24 80.75,66.24 79.73,65.23 78.33,65.23 | 98.02,60.15 96.75,58.88 93.19,58.88 90.4,56.08 v90.4,53.8 | v90.14,27.38 89.89,27.13 82.02,27.13 79.48,24.59 76.43,24.59
  Bottom 0.305: 5.31,41.1 6.58,39.83 13.56,39.83 14.83,38.56 15.47,38.56 16.1,38.56 17.37,37.29 20.55,37.29 21.82,36.02 33.25,36.02 34.52,37.29 38.33,37.29 | v19.91,89.99 14.2,89.99 12.29,88.09 9.75,88.09 7.21,85.55 v6.58,85.55 | 78.33,65.23 73.89,65.23 71.98,63.32 59.41,63.32 56.62,60.53 53.19,60.53 52.3,61.42 49.76,61.42 v44.68,56.34
/VPA  (via drill 0.61 pad 1.02)
  Top 0.254: 86.59,47.45 v86.59,51.51 | v100.56,75.9 100.56,62.69 99.54,61.67 99.54,57.35 100.56,56.34 100.56,53.29 98.78,51.51 v98.27,51.51
  Bottom 0.254: v100.56,75.9 97.76,75.9 97,76.66 84.81,76.66 84.56,76.91 82.02,76.91 81,77.93 78.33,77.93 | v86.59,51.51 v98.27,51.51
/WR  (via drill 0.61 pad 1.02)
  Top 0.254: v145.77,23.06 145.77,29.16 145.01,29.92 145.01,34.11 144.25,34.87 v144.25,37.29 144.25,46.69 v144.75,47.19 144.75,60.53 144.5,60.78 144.5,62.05 144.75,62.31 v144.75,64.72 | v112.12,23.06 112.12,23.44 111.23,24.33 111.23,41.99 110.21,43 110.21,49.48 109.19,50.5 v109.19,51
  Bottom 0.254: 151.36,18.24 151.36,19.51 147.04,19.51 145.77,20.78 v145.77,23.06 v112.12,23.06 | v144.75,47.19 147.55,47.19 147.55,52.53 149.58,52.53 150.85,53.8 151.36,53.8 | v144.75,64.72 146.66,64.72 147.55,65.61 147.55,70.31 149.45,70.31 150.72,71.58 151.36,71.58 | 151.36,36.02 151.36,36.53 150.6,37.29 v144.25,37.29 | v109.19,51 107.92,51 106.53,49.61 100.94,49.61 99.29,47.96 99.29,47.45
A0  (via drill 0.61 pad 1.02)
  Top 0.254: 76.43,14.43 74.27,16.59 74.27,30.81 72.36,32.72 72.36,53.67 72.49,53.8 v72.49,56.08 | 126.97,30.94 125.96,30.94 | 108.18,67.77 108.18,68.53 109.7,70.05 109.7,93.04 v110.85,94.18 | 126.97,30.94 126.97,47.7 125.96,48.72 126.97,49.73 126.97,65.48 125.96,66.5 126.97,67.51 126.97,70.05 126.47,70.56 126.47,83.77 125.96,84.28 127.48,85.8 127.48,92.66 v129.01,94.18 | 114.53,9.86 113.26,9.86 112.5,10.62 v110.72,10.62 | 126.97,30.94 127.23,30.68 127.23,14.17
  Top 0.305: 114.53,9.86 115.29,10.62 117.07,10.62 120.62,14.17 127.23,14.17
  Bottom 0.254: v72.49,56.08 54.08,56.08 52.55,57.61 51.03,57.61 | 76.43,14.43 77.44,13.41 97.51,13.41 98.02,13.92 99.8,13.92 103.1,10.62 v110.72,10.62 | v110.85,94.18 123.93,94.18 124.43,93.68 128.5,93.68 v129.01,94.18
A1  (via drill 0.61 pad 1.02)
  Top 0.254: v77.7,49.99 77.44,49.73 77.44,30.43 77.7,30.18 77.7,16.97 | 128.5,84.28 128.5,82.25 127.23,80.98 127.23,71.07 127.48,70.82 127.48,67.51 128.5,66.5 128.5,53.29 127.48,52.27 127.48,49.73 128.5,48.72 127.99,48.21 127.99,35 127.48,34.49 127.48,31.95 128.5,30.94 v128.5,26.37 | 104.11,67.77 105.64,67.77 | v70.84,88.09 70.84,94.95 70.08,95.71 | 104.11,67.77 104.11,55.32 104.37,55.07 104.37,49.99 105.38,48.97 105.38,44.02 103.86,42.49 v103.86,25.6 | v77.95,11.89 77.95,16.71 77.7,16.97 | v97.51,11.89 v97.51,25.6 | 77.7,16.97 76.43,16.97 | v104.11,88.09 104.37,87.83 104.37,80.59 104.11,80.34 104.11,67.77
  Bottom 0.254: v77.7,49.99 77.44,50.24 57.12,50.24 56.62,50.75 54.58,50.75 52.55,48.72 48.49,48.72 48.49,55.07 51.03,55.07 | v128.5,26.37 127.61,25.48 112.12,25.48 111.23,26.37 109.45,26.37 108.69,25.6 v103.86,25.6 v97.51,25.6 | v77.95,11.89 78.46,12.4 97.26,12.4 97.51,12.14 v97.51,11.89 | v104.11,88.09 v70.84,88.09
A2  (via drill 0.61 pad 1.02)
  Top 0.254: v73.38,52.78 72.87,52.27 72.87,40.84 v74.9,38.81 | v141.71,78.69 141.71,70.31 142.21,69.8 142.21,67.26 142.47,67.01 v142.47,65.61 | v102.59,91.64 102.59,87.33 102.08,86.82 v102.08,84.28 | v67.54,91.26 67.54,95.71 | 131.04,66.5 131.29,66.24 131.29,56.34 v131.55,56.34 131.55,52.78 132.05,52.27 132.05,50.75 131.04,49.73 131.04,48.72 131.55,48.21 v131.55,38.68 132.31,37.92 132.31,32.84 131.04,31.57 131.04,30.94
  Bottom 0.254: v73.38,52.78 65,52.78 65,55.58 53.57,55.58 51.03,53.04 51.03,52.53 | v74.9,38.81 75.41,38.3 102.84,38.3 103.23,38.68 v131.55,38.68 | 108.18,70.31 114.27,70.31 114.53,70.56 124.69,70.56 124.69,67.77 129.01,67.77 130.28,66.5 131.04,66.5 131.04,65.74 131.8,64.97 141.83,64.97 v142.47,65.61 | 131.04,85.29 134.34,85.29 134.59,85.04 134.59,80.21 136.12,78.69 v141.71,78.69 | 131.04,85.29 131.04,84.28 | v67.54,91.26 70.59,91.26 72.75,89.1 93.19,89.1 94.97,90.88 101.83,90.88 v102.59,91.64 | v102.08,84.28 106.4,84.28 107.67,85.55 130.78,85.55 131.04,85.29 | 106.91,55.07 107.42,55.07 108.94,56.59 116.81,56.59 117.07,56.34 v131.55,56.34
A3  (via drill 0.61 pad 1.02)
  Top 0.254: v56.87,30.94 56.87,37.54 52.81,37.54 52.55,37.8 52.55,48.46 51.03,49.99 | v78.71,25.98 83.41,25.98 v85.06,24.33 | v94.97,24.33 v94.97,29.67 | v66.52,82.75 66.52,94.18 65,95.71 | v97.51,87.07 99.03,87.07 v99.03,70.31 | v111.73,69.29 v111.73,63.2 v111.73,47.45 111.73,35.51 112.37,34.87 v112.37,30.3 | v133.58,62.43 133.58,66.5 133.58,67.51 134.59,68.53 134.59,69.8 133.58,70.82 133.58,84.28
  Bottom 0.254: v56.87,30.94 57.12,31.19 76.94,31.19 78.71,29.41 v78.71,25.98 | v85.06,24.33 v94.97,24.33 | v94.97,29.67 95.22,29.41 111.61,29.41 112.37,30.18 v112.37,30.3 113,29.67 118.85,29.67 119.1,29.92 132.56,29.92 133.58,30.94 | 133.58,48.72 132.31,47.45 v111.73,47.45 | v111.73,69.29 106.65,69.29 105.64,70.31 v99.03,70.31 | v66.52,82.75 66.52,83.26 80.87,83.26 81.89,84.28 88.62,84.28 88.87,84.53 96.24,84.53 96.75,85.04 96.75,86.31 v97.51,87.07 | v111.73,63.2 113.13,63.2 113.89,62.43 v133.58,62.43
A4  (via drill 0.61 pad 1.02)
  Top 0.254: 136.12,84.28 v136.12,72.59 136.12,70.94 137.13,69.93 137.13,68.28 136.12,67.26 136.12,66.5 136.12,60.53 136.63,60.02 136.63,52.53 137.13,52.02 137.13,50.62 136.12,49.61 136.12,48.72 136.12,37.29 137.39,36.02 137.39,33.1 136.12,31.83 136.12,30.94 v136.12,17.73 | v91.67,92.15 91.41,91.9 91.41,80.21 v91.67,79.96 | v103.1,75.39 v103.1,80.47 | v62.46,93.29 62.46,95.71 | v55.85,35.76 55.85,37.03 52.3,37.03 52.04,37.29 52.04,46.43 51.03,47.45 | v66.27,34.11 66.27,29.92 67.28,28.91 v67.28,15.7
  Bottom 0.254: v136.12,72.59 135.86,72.85 108.18,72.85 106.91,74.12 104.37,74.12 v103.1,75.39 | v62.46,93.29 71.22,93.29 74.4,90.12 89.64,90.12 v91.67,92.15 | v91.67,79.96 91.67,80.47 v103.1,80.47 | v55.85,35.76 56.11,36.02 66.27,36.02 v66.27,34.11 | v67.28,15.7 78.21,15.7 79.98,13.92 90.14,13.92 90.78,14.55 90.78,17.22 92.3,18.75 111.99,18.75 113,17.73 v136.12,17.73
A5  (via drill 0.61 pad 1.02)
  Top 0.254: v55.35,44.91 58.9,44.91 60.05,46.05 60.05,54.94 60.93,55.83 61.95,55.83 62.46,56.34 62.46,59.39 63.22,60.15 v63.22,61.16 | v69.32,61.16 69.82,61.16 69.82,78.94 68.81,79.96 v68.81,94.44 | 109.7,66.75 109.96,66.75 109.96,56.46 109.58,56.08 v109.58,55.07 | 138.66,30.94 138.66,31.7 139.67,32.72 139.67,33.99 138.91,34.75 138.91,48.46 138.66,48.72 138.66,49.48 139.67,50.5 139.67,52.4 139.17,52.91 139.17,65.99 138.66,66.5 138.66,67.26 139.67,68.28 139.67,69.8 138.66,70.82 138.66,84.28 | v88.11,91.64 v88.11,87.07 | v94.21,87.07 94.46,86.82 94.46,81.99 94.97,81.48 v94.97,68.28 | 109.7,66.75 107.42,66.75 107.16,67.01 107.16,69.04 106.91,69.29 106.91,71.07 105.64,72.34 105.64,72.85 | v109.7,68.28 109.7,66.75
  Bottom 0.254: v63.22,61.16 v69.32,61.16 | 51.03,44.91 v55.35,44.91 | 59.92,95.71 61.19,94.44 v68.81,94.44 71.6,94.44 75.41,90.63 87.1,90.63 v88.11,91.64 | 138.66,48.72 137.39,49.99 137.39,52.53 136.25,53.67 123.8,53.67 122.78,54.69 115.29,54.69 114.91,55.07 v109.58,55.07 | v88.11,87.07 v94.21,87.07 | v94.97,68.28 104.37,68.28 104.88,68.78 109.19,68.78 v109.7,68.28
A6  (via drill 0.61 pad 1.02)
  Top 0.254: 141.2,30.94 142.21,31.95 142.21,35.38 141.2,36.4 141.2,48.72 142.21,49.73 142.21,52.27 141.71,52.78 141.71,64.85 141.2,65.35 141.2,66.5 | v137.13,73.74 137.13,77.17 136.75,77.55 136.75,80.72 137.64,81.61 137.64,91.9 139.93,91.9 139.93,86.31 141.2,85.04 141.2,84.28 | v49.5,51.26 49.5,43.89 51.03,42.37 | v62.71,52.78 62.71,55.32 63.22,55.83 63.98,55.83 65,56.85 65,66.37 66.65,68.02 v66.65,75.13
  Bottom 0.254: v49.5,51.26 52.81,51.26 52.81,53.54 53.7,54.43 56.24,54.43 57.89,52.78 v62.71,52.78 | v66.65,75.13 67.79,76.28 73.38,76.28 75.29,74.37 85.7,74.37 86.46,73.61 99.54,73.61 102.34,76.4 107.16,76.4 108.18,75.39 109.83,73.74 v137.13,73.74 137.13,73.36 139.93,70.56 139.93,67.77 141.2,66.5
A7  (via drill 0.61 pad 1.02)
  Top 0.254: 106.91,83.01 106.91,83.13 | 106.91,83.01 106.91,83.52 107.92,84.53 v108.69,84.53 | v112.75,84.53 113,84.79 113,93.93 113.26,94.18 115.04,94.18 v115.04,90.63 | 143.74,30.94 142.72,31.95 142.72,34.24 143.23,34.75 143.23,43.51 | v55.09,39.57 60.17,39.57 v60.17,44.65 | v93.07,42.11 93.32,42.11 95.1,43.89 97.76,43.89 98.02,44.15 98.02,46.18 100.05,46.18 100.56,45.67 100.56,44.15 102.08,42.62 v102.59,42.62 | v143.23,43.64 143.23,43.51 | 143.74,84.28 144.25,83.77 144.25,76.66 143.74,76.15 143.74,70.82 142.72,69.8 142.72,67.51 143.74,66.5 143.74,53.29 142.72,52.27 142.72,49.73 143.74,48.72 143.74,47.19 143.23,46.69 143.23,43.51 | 106.91,83.01 106.91,77.29 105.64,76.02 105.64,75.39
  Bottom 0.254: v112.75,84.53 v108.69,84.53 | 143.74,84.28 142.47,83.01 140.44,83.01 139.93,83.52 139.93,84.79 137.39,87.33 137.39,88.6 136.88,89.1 134.85,89.1 134.85,87.33 134.59,87.07 133.07,87.07 132.31,87.83 132.31,89.36 131.55,90.12 123.93,90.12 122.91,91.14 115.54,91.14 v115.04,90.63 | v55.09,39.57 54.84,39.83 51.03,39.83 | v60.17,44.65 60.17,44.15 84.81,44.15 86.33,42.62 87.86,42.62 88.37,42.11 v93.07,42.11 | v102.59,42.62 102.59,43.13 112.75,43.13 113.26,43.64 v143.23,43.64
A8
  Top 0.254: 141.2,15.7 141.2,29.03 140.18,30.05 140.18,31.45 141.2,32.46 141.2,33.48 141.2,34.75 140.44,35.51 140.44,47.45 140.18,47.7 140.18,49.35 141.2,50.37 141.2,51.26 141.2,52.4 140.69,52.91 140.69,64.72 140.18,65.23 140.18,67.01 140.69,67.51 140.69,68.53 141.2,69.04
  Bottom 0.254: 63.73,19.51 66.78,19.51 68.05,20.78 69.57,20.78 70.33,20.02 75.92,20.02 76.43,19.51 76.94,19 85.95,19 89.51,22.56 105.51,22.56 106.02,22.05 138.15,22.05 141.2,19 141.2,15.7 | 141.2,69.04 141.2,70.31 138.66,72.85 138.66,73.61 134.34,77.93 108.18,77.93
A9  (via drill 0.61 pad 1.02)
  Top 0.254: 138.66,69.04 138.15,68.53 138.15,67.51 137.64,67.01 137.64,64.59 138.15,64.08 v138.15,60.4 138.15,52.78 138.66,52.27 138.66,51.26 138.66,50.37 137.64,49.35 137.64,47.83 138.15,47.32 138.15,33.99 138.66,33.48 138.66,33.1 137.52,31.95 137.52,16.84 138.66,15.7 | v88.75,64.97 88.75,74.75 87.99,75.51 v87.99,77.93 | v74.9,32.59 74.9,23.57 76.43,22.05 | v96.49,30.3 v96.49,19.76
  Bottom 0.254: v88.75,64.97 92.68,64.97 94.21,63.45 94.21,61.67 106.91,61.67 108.56,60.02 109.96,60.02 110.34,60.4 v138.15,60.4 | v87.99,77.93 105.64,77.93 | 63.73,22.05 67.28,22.05 68.55,23.32 74.4,23.32 75.67,22.05 76.43,22.05 | v74.9,32.59 76.68,32.59 79.6,29.67 88.87,29.67 89.89,30.68 96.11,30.68 v96.49,30.3 | v96.49,19.76 97,19.25 137.9,19.25 138.66,18.49 138.66,15.7
A10  (via drill 0.61 pad 1.02)
  Top 0.254: 131.04,15.7 130.53,16.21 130.53,29.67 130.02,30.18 130.02,32.46 131.04,33.48 130.53,33.99 130.53,47.19 130.02,47.7 130.02,50.24 131.04,51.26 130.53,51.77 130.53,65.35 130.02,65.86 130.02,69.04 | 130.02,69.04 131.04,69.04 | 130.02,69.04 v130.02,78.94
  Bottom 0.254: v130.02,78.94 128.24,78.94 126.21,80.98 116.31,80.98 115.8,80.47 108.18,80.47
A11  (via drill 0.61 pad 1.02)
  Top 0.254: 136.12,15.7 134.85,16.97 134.85,32.21 136.12,33.48 136.12,35.38 135.1,36.4 135.1,50.75 135.61,51.26 | 135.61,51.26 136.12,51.26 | 136.12,69.04 136.12,68.28 135.1,67.26 135.1,65.48 135.61,64.97 v135.61,59.39 135.61,51.26 | v107.16,59.39 107.16,60.27 106.65,60.78 106.65,68.28 105.89,69.04 105.13,69.04 104.62,69.55 104.62,79.45 105.64,80.47
  Bottom 0.254: v135.61,59.39 v107.16,59.39
A12  (via drill 0.61 pad 1.02)
  Top 0.254: 146.28,84.28 146.28,71.32 145.26,70.31 145.26,67.51 146.28,66.5 145.77,65.99 145.77,61.93 145.52,61.67 v145.52,61.42 145.52,52.4 145.26,52.15 145.26,49.73 146.28,48.72 146.28,35.26 147.29,34.24 147.29,31.95 146.28,30.94 | v112.62,61.29 112.62,61.67 112.75,61.8 v112.75,83.01
  Bottom 0.254: v112.62,61.29 112.75,61.42 v145.52,61.42 | v112.75,83.01 108.18,83.01
A13  (via drill 0.61 pad 1.02)
  Top 0.254: 153.9,28.4 152.88,29.41 152.88,45.16 153.9,46.18 152.88,47.19 152.88,62.94 153.9,63.96 | v141.96,81.99 142.21,81.99 142.21,85.29 141.71,85.8 141.71,87.58 141.2,88.09 140.69,88.6 140.69,94.18 139.93,94.95 139.93,97.49 122.4,97.49 v122.4,89.36 | v105.64,88.09 105.64,85.55 | v157.71,65.23 157.96,65.48 157.96,80.47 157.71,80.72 154.91,80.72 153.9,81.74
  Bottom 0.254: 153.9,81.74 152.63,83.01 146.53,83.01 145.52,81.99 v141.96,81.99 | v105.64,88.09 106.65,89.1 116.31,89.1 116.56,89.36 v122.4,89.36 | v157.71,65.23 155.17,65.23 153.9,63.96
A14  (via drill 0.61 pad 1.02)
  Top 0.254: v107.16,87.96 107.16,85.04 105.64,83.52 105.64,83.01 | v111.99,90.63 v111.99,87.96 | v138.66,90.88 138.66,88.09 138.66,86.06 139.93,84.79 139.93,83.52 139.29,82.88 139.29,74.75 v139.67,74.37 | 148.82,20.78 149.83,21.79 149.83,37.54 148.82,38.56 148.31,39.07 147.55,39.07 147.17,39.45 147.17,47.96 147.55,48.34 147.55,56.34 | 147.55,56.34 148.82,56.34 | 148.82,74.12 147.8,73.1 147.8,64.59 147.17,63.96 147.17,56.72 147.55,56.34
  Bottom 0.254: v111.99,87.96 v107.16,87.96 | v111.99,90.63 113,91.64 123.16,91.64 123.93,90.88 v138.66,90.88 | v139.67,74.37 139.93,74.12 148.82,74.12
A15  (via drill 0.61 pad 1.02)
  Top 0.254: 149.83,61.42 148.82,61.42 | v145.26,35.64 v145.26,43.64 | 149.83,61.42 149.83,47.7 149.33,47.19 149.33,44.15 148.82,43.64 | v148.82,81.99 148.82,79.2 149.83,78.18 149.83,61.42
  Bottom 0.254: 135.1,85.8 135.36,85.8 135.61,86.06 135.61,87.58 136.12,88.09 | 103.1,85.55 104.11,86.56 106.65,86.56 107.16,86.06 131.29,86.06 131.55,85.8 135.1,85.8 | v145.26,35.64 145.26,29.67 152.63,29.67 152.63,27.13 150.09,27.13 148.82,25.86 | v145.26,43.64 148.82,43.64 | 135.1,85.8 135.1,80.98 145.52,80.98 146.53,81.99 v148.82,81.99
A16  (via drill 0.61 pad 1.02)
  Top 0.254: v132.56,81.74 132.56,85.29 133.07,85.8 133.07,87.58 133.58,88.09 | 151.36,30.94 150.34,31.95 150.34,47.19 151.36,48.21 151.36,48.72 150.34,49.73 150.34,66.5 | 150.34,66.5 151.36,66.5 | 151.36,84.28 150.34,83.26 150.34,66.5
  Bottom 0.254: v132.56,81.74 132.31,81.99 115.8,81.99 115.54,81.74 110.46,81.74 110.21,81.99 104.11,81.99 103.1,83.01 | 133.58,88.09 133.58,89.87 139.93,89.87 139.93,86.82 140.94,85.8 149.83,85.8 151.36,84.28
A17  (via drill 0.61 pad 1.02)
  Top 0.254: v142.47,17.22 v142.47,29.03 | v145.01,90.37 v145.01,75.39 | v131.04,91.9 131.04,88.09 131.04,86.31 132.05,85.29 132.05,83.52 131.67,83.13 131.67,71.7 132.31,71.07 132.31,68.66 132.05,68.4 132.05,57.99 v132.69,57.35 132.69,52.4 132.56,52.27 132.56,50.37 132.05,49.86 132.05,46.56 132.44,46.18 v132.44,40.97 | v104.11,91.9 103.35,92.66 102.08,92.66 101.57,92.15 101.57,86.56 100.56,85.55
  Bottom 0.254: v142.47,17.22 152.88,17.22 153.9,18.24 | 142.47,40.97 146.79,40.97 147.93,39.83 151.87,39.83 152.12,39.57 157.71,39.57 157.71,37.29 155.17,37.29 153.9,36.02 | v132.69,57.35 155.17,57.35 155.17,55.07 153.9,53.8 | v145.01,75.39 154.91,75.39 154.91,72.59 153.9,71.58 | v142.47,29.03 142.47,40.97 | v145.01,90.37 145.01,91.9 v131.04,91.9 130.78,91.64 123.93,91.64 123.42,92.15 112.5,92.15 111.99,91.64 104.37,91.64 v104.11,91.9 | 142.47,40.97 v132.44,40.97
A18  (via drill 0.61 pad 1.02)
  Top 0.254: v129.51,28.4 v129.51,45.67 v129.51,63.45 129.51,76.66 127.99,78.18 127.99,79.96 128.24,80.21 v129.51,80.21 129.51,85.29 128.5,86.31 128.5,88.09
  Bottom 0.254: v129.51,45.67 134.72,45.67 135.23,46.18 151.36,46.18 | v129.51,63.45 150.85,63.45 151.36,63.96 | 100.56,83.01 102.08,81.48 109.7,81.48 110.08,81.1 115.67,81.1 116.05,81.48 126.72,81.48 127.99,80.21 v129.51,80.21 133.45,80.21 135.48,78.18 139.55,78.18 140.06,77.67 143.61,77.67 146.79,80.85 149.58,80.85 150.47,81.74 151.36,81.74 | 151.36,28.4 148.69,28.4 146.41,26.11 131.8,26.11 v129.51,28.4
A19  (via drill 0.61 pad 1.02)
  Top 0.254: v124.69,94.69 125.96,93.42 125.96,88.09 | v113.26,95.2 110.21,95.2 108.43,93.42 101.83,93.42 100.56,92.15 v100.56,87.07
  Bottom 0.254: v100.56,87.07 99.54,87.07 98.02,85.55 | v113.26,95.2 113.77,94.69 v124.69,94.69
A20  (via drill 0.61 pad 1.02)
  Top 0.254: v122.4,76.91 122.4,85.29 123.42,86.31 123.42,88.09 | v98.02,76.91 98.02,83.01
  Bottom 0.254: v98.02,76.91 v122.4,76.91
A21  (via drill 0.61 pad 1.02)
  Top 0.254: v119.86,78.94 119.86,87.07 120.88,88.09
  Bottom 0.254: v119.86,78.94 104.88,78.94 104.37,78.44 90.65,78.44 90.65,80.72 91.29,81.36 93.83,81.36 95.48,83.01
A22
  Top 0.254: 92.94,85.55 92.94,87.58 93.45,88.09 93.45,92.28 97.89,96.72 113.51,96.72 114.53,95.71 114.53,95.2 115.04,94.69 115.54,94.69 118.34,91.9 118.34,88.09
A23  (via drill 0.61 pad 1.02)
  Top 0.254: v117.07,79.83 117.07,85.04 115.8,86.31 115.8,88.09 | v92.94,79.45 92.94,83.01
  Bottom 0.254: v92.94,79.45 116.69,79.45 v117.07,79.83
AX0
  Bottom 0.305: 5.31,51.26 6.58,49.99 13.56,49.99 14.83,48.72 15.47,48.72 16.1,48.72 17.37,47.45 20.55,47.45 21.82,46.18 31.98,46.18 33.25,47.45 38.33,47.45 38.96,47.45 40.23,48.72 44.04,48.72 44.68,49.35 44.68,50.62 44.04,51.26 40.23,51.26 39.6,51.89 39.6,53.16 37.69,55.07 37.69,58.5 39.34,60.15 40.87,60.15 43.41,60.15
AX1
  Bottom 0.305: 5.31,48.72 6.58,47.45 13.56,47.45 14.83,46.18 15.47,46.18 16.1,46.18 17.37,44.91 20.55,44.91 21.82,43.64 32.61,43.64 33.88,44.91 38.33,44.91 38.96,44.91 40.23,46.18 44.68,46.18 45.31,46.81 45.31,52.53 44.04,53.8 40.23,53.8 38.96,55.07 38.96,56.34 40.23,57.61 40.87,57.61 43.41,57.61
AX2
  Bottom 0.305: 5.31,46.18 6.58,44.91 13.56,44.91 14.83,43.64 15.47,43.64 16.1,43.64 17.37,42.37 20.55,42.37 21.82,41.1 33.88,41.1 35.15,42.37 38.33,42.37 38.96,42.37 40.23,43.64 45.31,43.64 45.95,44.27 45.95,54.43 45.31,55.07 43.41,55.07 40.87,55.07
AX3
  Top 0.305: 38.33,39.83 40.23,39.83 42.14,41.73 42.14,52.53 43.41,52.53
  Bottom 0.305: 5.31,43.64 6.58,42.37 13.56,42.37 14.83,41.1 15.47,41.1 16.1,41.1 17.37,39.83 20.55,39.83 21.82,38.56 32.61,38.56 33.88,39.83 38.33,39.83 | 43.41,52.53 40.87,52.53
AX4
  Bottom 0.305: 5.31,53.8 6.58,52.53 13.56,52.53 14.83,51.26 15.47,51.26 16.1,51.26 17.37,49.99 20.55,49.99 21.82,48.72 38.96,48.72 40.23,49.99 40.87,49.99 43.41,49.99
AX5  (via drill 0.61 pad 1.02)
  Top 0.305: v25.31,51.26 v25.31,44.91
  Bottom 0.305: 43.41,47.45 40.87,47.45 40.23,47.45 38.96,46.18 33.25,46.18 31.98,44.91 v25.31,44.91 | 5.31,56.34 6.58,55.07 13.56,55.07 14.83,53.8 15.47,53.8 16.1,53.8 17.37,52.53 20.55,52.53 21.82,51.26 v25.31,51.26
AX6  (via drill 0.61 pad 1.02)
  Top 0.305: v33.88,51.89 v33.88,43
  Bottom 0.305: 43.41,44.91 40.87,44.91 40.23,44.91 38.96,43.64 34.52,43.64 v33.88,43 | 5.31,58.88 6.58,57.61 13.56,57.61 14.83,56.34 15.47,56.34 16.1,56.34 17.37,55.07 30.71,55.07 v33.88,51.89
AX7  (via drill 0.61 pad 1.02)
  Top 0.305: v35.79,53.8 v35.79,41.1
  Bottom 0.305: 43.41,42.37 40.87,42.37 39.6,41.1 v35.79,41.1 | 5.31,61.42 6.58,60.15 13.56,60.15 14.83,58.88 15.47,58.88 16.1,58.88 17.37,57.61 31.98,57.61 v35.79,53.8
CA1
  Bottom 0.305: 10.39,58.88 13.56,58.88 14.83,57.61 16.1,57.61 17.37,56.34 18.01,56.34 31.34,56.34 35.15,52.53 38.33,52.53
CA2
  Bottom 0.305: 10.39,56.34 13.56,56.34 14.83,55.07 16.1,55.07 17.37,53.8 18.01,53.8 30.07,53.8 33.88,49.99 38.33,49.99
CB1
  Bottom 0.305: 10.39,13.16 12.93,13.16 14.2,11.89 16.1,11.89 17.37,10.62 18.01,10.62 20.55,10.62 21.82,9.35 23.09,9.35
CB2
  Bottom 0.305: 10.39,10.62 12.29,10.62 13.56,9.35 16.1,9.35 17.37,8.08 18.01,8.08 19.28,6.81 23.09,6.81
CPU_CLK  (via drill 0.61 pad 1.02)
  Top 0.254: v76.68,63.07 v76.68,71.32
  Bottom 0.254: v76.68,71.32 76.43,71.58 71.35,71.58 | 90.4,62.69 89.13,61.42 77.7,61.42 76.68,62.43 v76.68,63.07
CS2  (via drill 0.61 pad 1.02)
  Top 0.254: 153.9,23.32 154.91,24.33 154.91,40.08 153.9,41.1 154.91,42.11 154.91,58.88 | 154.91,58.88 153.9,58.88 | 154.91,58.88 154.91,75.64 153.9,76.66 | LED1. v105,42.11
  Top 0.305: LED1. 105,33.48 106.91,33.48
  Bottom 0.254: v105,42.11 105.26,42.37 113,42.37 113.77,43.13 140.69,43.13 141.71,42.11 152.37,42.11 153.39,41.1 153.9,41.1
CS_SCL
  Top 0.305: 68.81,27.13 68.81,29.67
D0  (via drill 0.61 pad 1.02)
  Top 0.254: 123.42,30.94 123.93,31.45 123.93,32.33 124.43,32.84 124.43,47.07 123.42,48.08 123.42,48.72 123.93,49.23 123.93,50.24 124.43,50.75 124.43,52.65 123.42,53.67 123.42,66.5 123.42,67.39 124.43,68.4 124.43,70.05 123.42,71.07 v123.42,71.58 123.42,84.28 | v65.13,23.32 65.13,14.43 68.81,14.43 | v98.53,12.9 v98.53,32.97 | v82.78,85.29 83.16,85.29 84.18,84.28 85.57,84.28 86.59,83.26 86.59,70.69 v86.97,70.31 85.7,69.04 84.05,69.04 82.78,67.77
  Bottom 0.254: v82.78,85.29 46.96,85.29 44.68,83.01 44.68,80.47 | 51.03,24.59 53.57,24.59 54.33,24.59 55.6,25.86 58.65,25.86 61.19,23.32 v65.13,23.32 | v98.53,32.97 98.53,32.46 121.89,32.46 123.42,30.94 | v98.53,12.9 72.87,12.9 71.35,14.43 68.81,14.43 | v86.97,70.31 94.59,70.31 95.86,71.58 99.67,71.58 100.18,71.07 102.72,71.07 103.23,71.58 v123.42,71.58
D1  (via drill 0.61 pad 1.02)
  Top 0.254: v48.74,87.07 47.22,85.55 47.22,80.47 | 120.88,30.94 120.88,31.95 121.89,32.97 121.89,45.42 121.13,46.18 121.13,48.46 120.88,48.72 120.88,49.48 121.89,50.5 121.89,52.02 121.13,52.78 121.13,66.24 120.88,66.5 120.88,67.26 121.89,68.28 121.89,69.8 120.88,70.82 120.88,84.28 | v54.58,32.21 54.58,25.86 52.81,25.86 52.55,25.6 52.55,23.06 53.57,22.05 | v81.64,86.56 81.25,86.56 81.25,71.58 | 81.25,71.58 81.25,70.69 81.76,70.18 81.76,61.67 82.52,60.91 82.52,46.43 v81.25,45.16 | v70.33,33.6 v70.33,45.16 | 85.32,70.31 84.05,71.58 81.25,71.58
  Bottom 0.254: 51.03,22.05 53.57,22.05 | v54.58,32.21 54.84,31.95 70.33,31.95 v70.33,33.6 76.56,33.6 77.44,34.49 80.24,34.49 80.24,31.95 119.86,31.95 120.88,30.94 | v70.33,45.16 v81.25,45.16 | v81.64,86.56 81.25,86.56 80.75,86.06 68.3,86.06 67.28,87.07 v48.74,87.07
D2  (via drill 0.61 pad 1.02)
  Top 0.254: 118.34,30.94 118.34,31.95 119.35,32.97 119.35,34.49 117.96,35.89 117.96,48.34 118.34,48.72 118.34,49.61 119.35,50.62 119.35,52.02 118.85,52.53 118.85,57.35 | 118.34,84.28 118.21,84.15 118.21,71.2 119.35,70.05 119.35,68.53 118.34,67.51 118.34,66.5 118.85,65.99 118.85,57.35 | v45.69,19.51 45.69,30.43 45.19,30.94 v36.8,30.94 | v33.5,57.35 32.49,56.34 32.49,39.57 33.25,38.81 v33.25,29.67 | v35.79,57.35 37.44,59 37.44,65.1 39.34,67.01 40.61,67.01 | 40.61,67.01 v42.14,67.01 | 49.76,69.16 49.76,80.47 | v48.49,69.16 49.76,69.16 | v118.59,57.35 118.85,57.35 | v91.41,71.32 91.41,69.8 90.65,69.04 90.65,67.77 91.41,67.01 91.41,57.1 92.94,55.58 v92.94,53.8 | 40.61,67.01 40.36,67.01 | 49.76,69.16 49.76,67.89 57.63,67.89 v58.39,67.13
  Bottom 0.254: 53.57,19.51 51.03,19.51 v45.69,19.51 | v36.8,30.94 35.03,30.94 33.76,29.67 v33.25,29.67 | v33.5,57.35 v35.79,57.35 | v42.14,67.01 42.39,67.26 46.46,67.26 48.49,69.29 v48.49,69.16 | v118.59,57.35 106.4,57.35 105.64,56.59 105.64,53.8 v92.94,53.8 | v58.39,67.13 59.16,67.89 60.3,67.89 60.93,67.26 67.54,67.26 67.79,67.51 67.79,72.72 76.81,72.72 77.95,71.58 81.51,71.58 82.78,70.31 83.79,71.32 v91.41,71.32
D3  (via drill 0.61 pad 1.02)
  Top 0.254: 115.8,15.7 115.8,29.16 116.81,30.18 116.81,32.46 115.8,33.48 115.8,47.32 116.81,48.34 116.81,51.26 | 116.81,51.26 115.8,51.26 | 116.81,51.26 116.81,67.26 115.8,68.28 115.8,69.04 | v49.12,58.62 48.49,57.99 48.49,39.32 53.31,34.49 55.35,34.49 55.6,34.24 55.6,31.19 55.09,30.68 55.09,21.67 54.2,20.78 52.3,20.78 52.3,18.24 53.57,16.97 | v103.1,73.61 v103.1,66.24 | v65.13,68.53 63.98,68.53 62.46,67.01 62.46,61.93 61.44,60.91 v61.44,60.66
  Bottom 0.254: 51.03,16.97 53.57,16.97 | 65.13,69.04 56.11,69.04 56.11,82.75 52.3,82.75 52.3,80.47 | v49.12,58.62 49.38,58.88 56.11,58.88 57.89,60.66 v61.44,60.66 | 65.13,69.04 66.27,69.04 66.27,72.59 69.19,75.51 72.49,75.51 74.14,73.86 84.3,73.86 85.32,72.85 99.92,72.85 100.69,73.61 v103.1,73.61 | v65.13,68.53 65.13,69.04 | v103.1,66.24 113,66.24 115.8,69.04
D4  (via drill 0.61 pad 1.02)
  Top 0.254: 117.58,51.26 118.34,51.26 | 118.34,69.04 117.32,68.02 117.32,65.74 117.58,65.48 117.58,51.26 | v102.08,67.26 v102.08,72.34 | v79.98,72.85 v79.98,87.07 | v54.84,88.09 54.84,80.47 | 53.57,14.43 54.84,13.16 57.89,13.16 58.65,12.4 58.65,10.62 58.39,10.36 v58.39,7.82 | v71.86,10.36 69.57,8.08 68.3,8.08 66.01,5.79 v66.01,5.66 | v103.29,8.84 v103.29,13.16 | v114.02,10.87 114.02,11.89 117.83,15.7 118.34,15.7 118.34,29.16 117.32,30.18 117.32,32.46 118.34,33.48 116.81,35 116.81,47.45 117.32,47.96 117.32,50.11 117.58,50.37 117.58,51.26
  Bottom 0.254: 53.57,14.43 51.03,14.43 | v102.08,72.34 86.46,72.34 85.95,71.83 83.79,71.83 82.78,72.85 v79.98,72.85 | v102.08,67.26 104.37,67.26 104.88,66.75 109.19,66.75 109.7,67.26 112.24,67.26 115.04,70.05 117.32,70.05 118.34,69.04 | v54.84,88.09 55.09,87.83 69.06,87.83 69.82,87.07 v79.98,87.07 | v103.29,8.84 100.3,8.84 98.78,10.36 88.37,10.36 87.35,11.38 79.98,11.38 78.97,10.36 v71.86,10.36 | v103.29,13.16 112.5,13.16 114.02,11.63 v114.02,10.87 | v58.39,7.82 59.41,6.81 61.44,6.81 62.59,5.66 v66.01,5.66
D5  (via drill 0.61 pad 1.02)
  Top 0.254: 120.88,15.7 120.37,16.21 120.37,29.92 119.86,30.43 119.86,31.7 120.37,32.21 120.37,32.97 120.88,33.48 120.88,45.42 119.86,46.43 119.86,49.35 120.88,50.37 120.88,51.26 120.37,51.77 120.37,65.48 119.86,65.99 119.86,67.39 120.88,68.4 120.88,69.04 | v45.44,77.93 45.44,69.67 44.68,68.91 44.68,61.29 39.34,61.29 39.34,55.83 36.8,53.29 36.8,40.34 35.53,39.07 35.53,13.16 v44.93,13.16 | v98.02,52.78 98.02,56.34 99.03,57.35 99.03,62.18 99.29,62.43 99.29,65.86 98.15,67.01 v98.15,74.63
  Bottom 0.254: 120.88,51.26 119.61,52.53 106.91,52.53 106.65,52.78 v98.02,52.78 | 53.57,11.89 51.03,11.89 44.93,11.89 v44.93,13.16 | v45.44,77.93 45.44,79.45 45.95,79.96 45.95,83.01 47.09,84.15 57.38,84.15 57.38,80.47 57.38,78.18 58.01,77.55 77.06,77.55 77.7,76.91 80.49,76.91 81,76.4 83.79,76.4 84.81,75.39 U2. 86.46,75.39 87.6,74.24 97.76,74.24 v98.15,74.63
D6  (via drill 0.61 pad 1.02)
